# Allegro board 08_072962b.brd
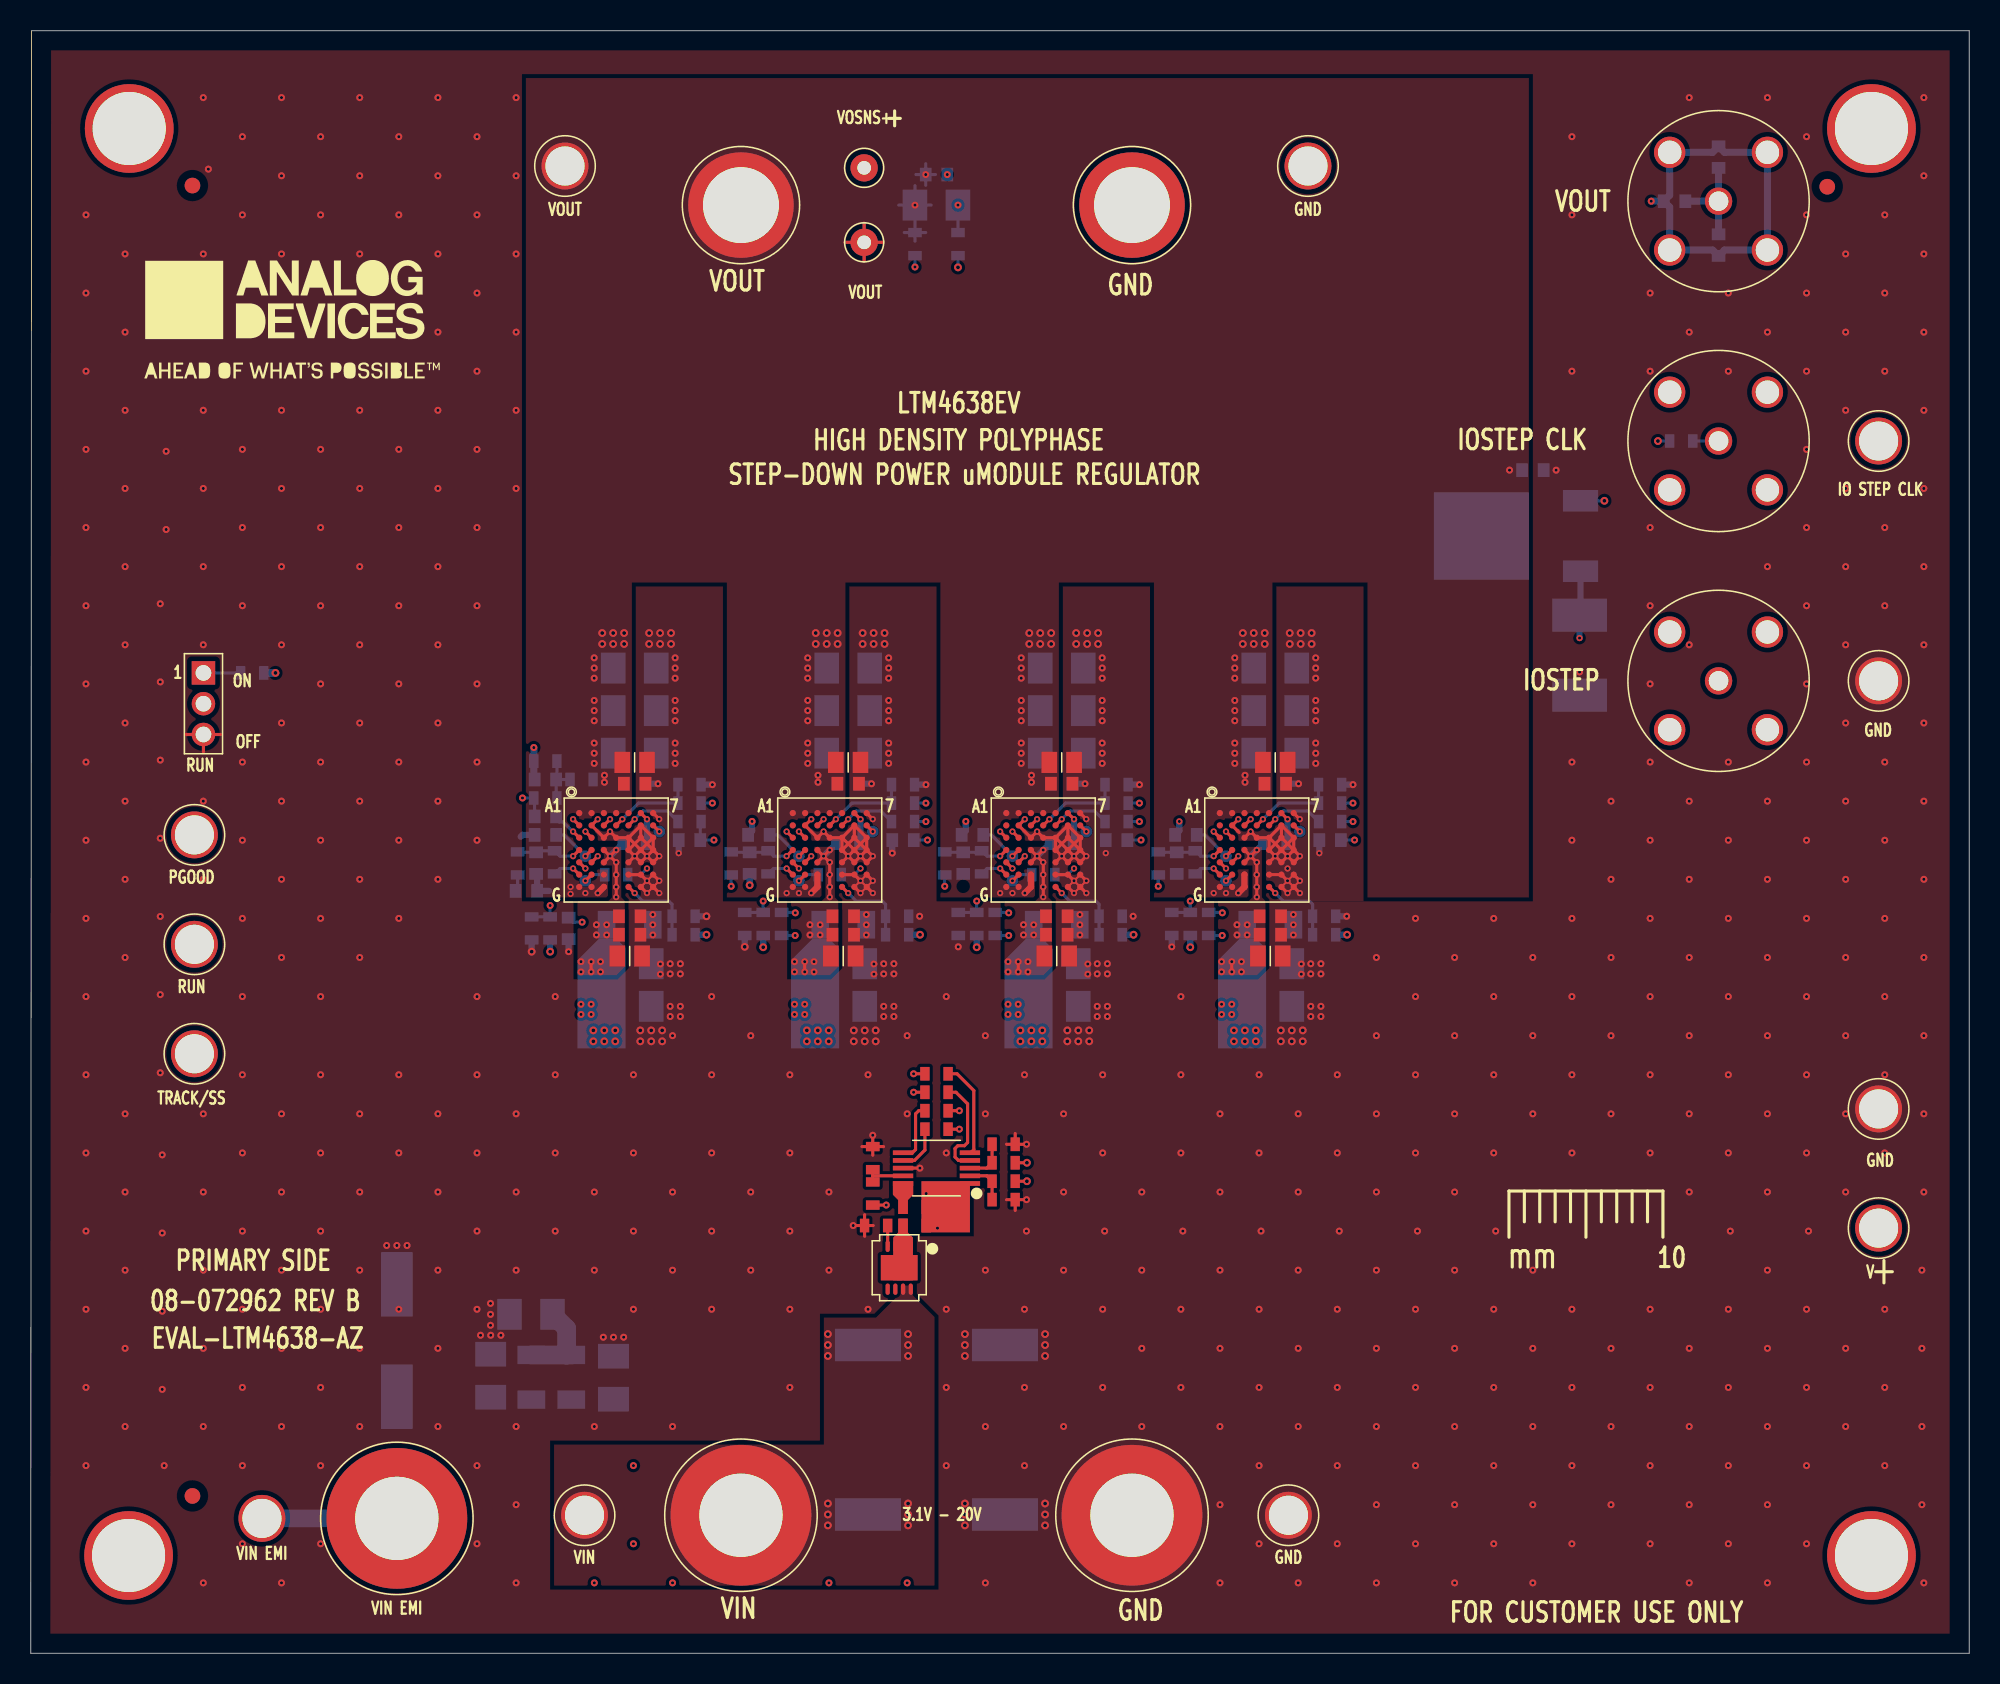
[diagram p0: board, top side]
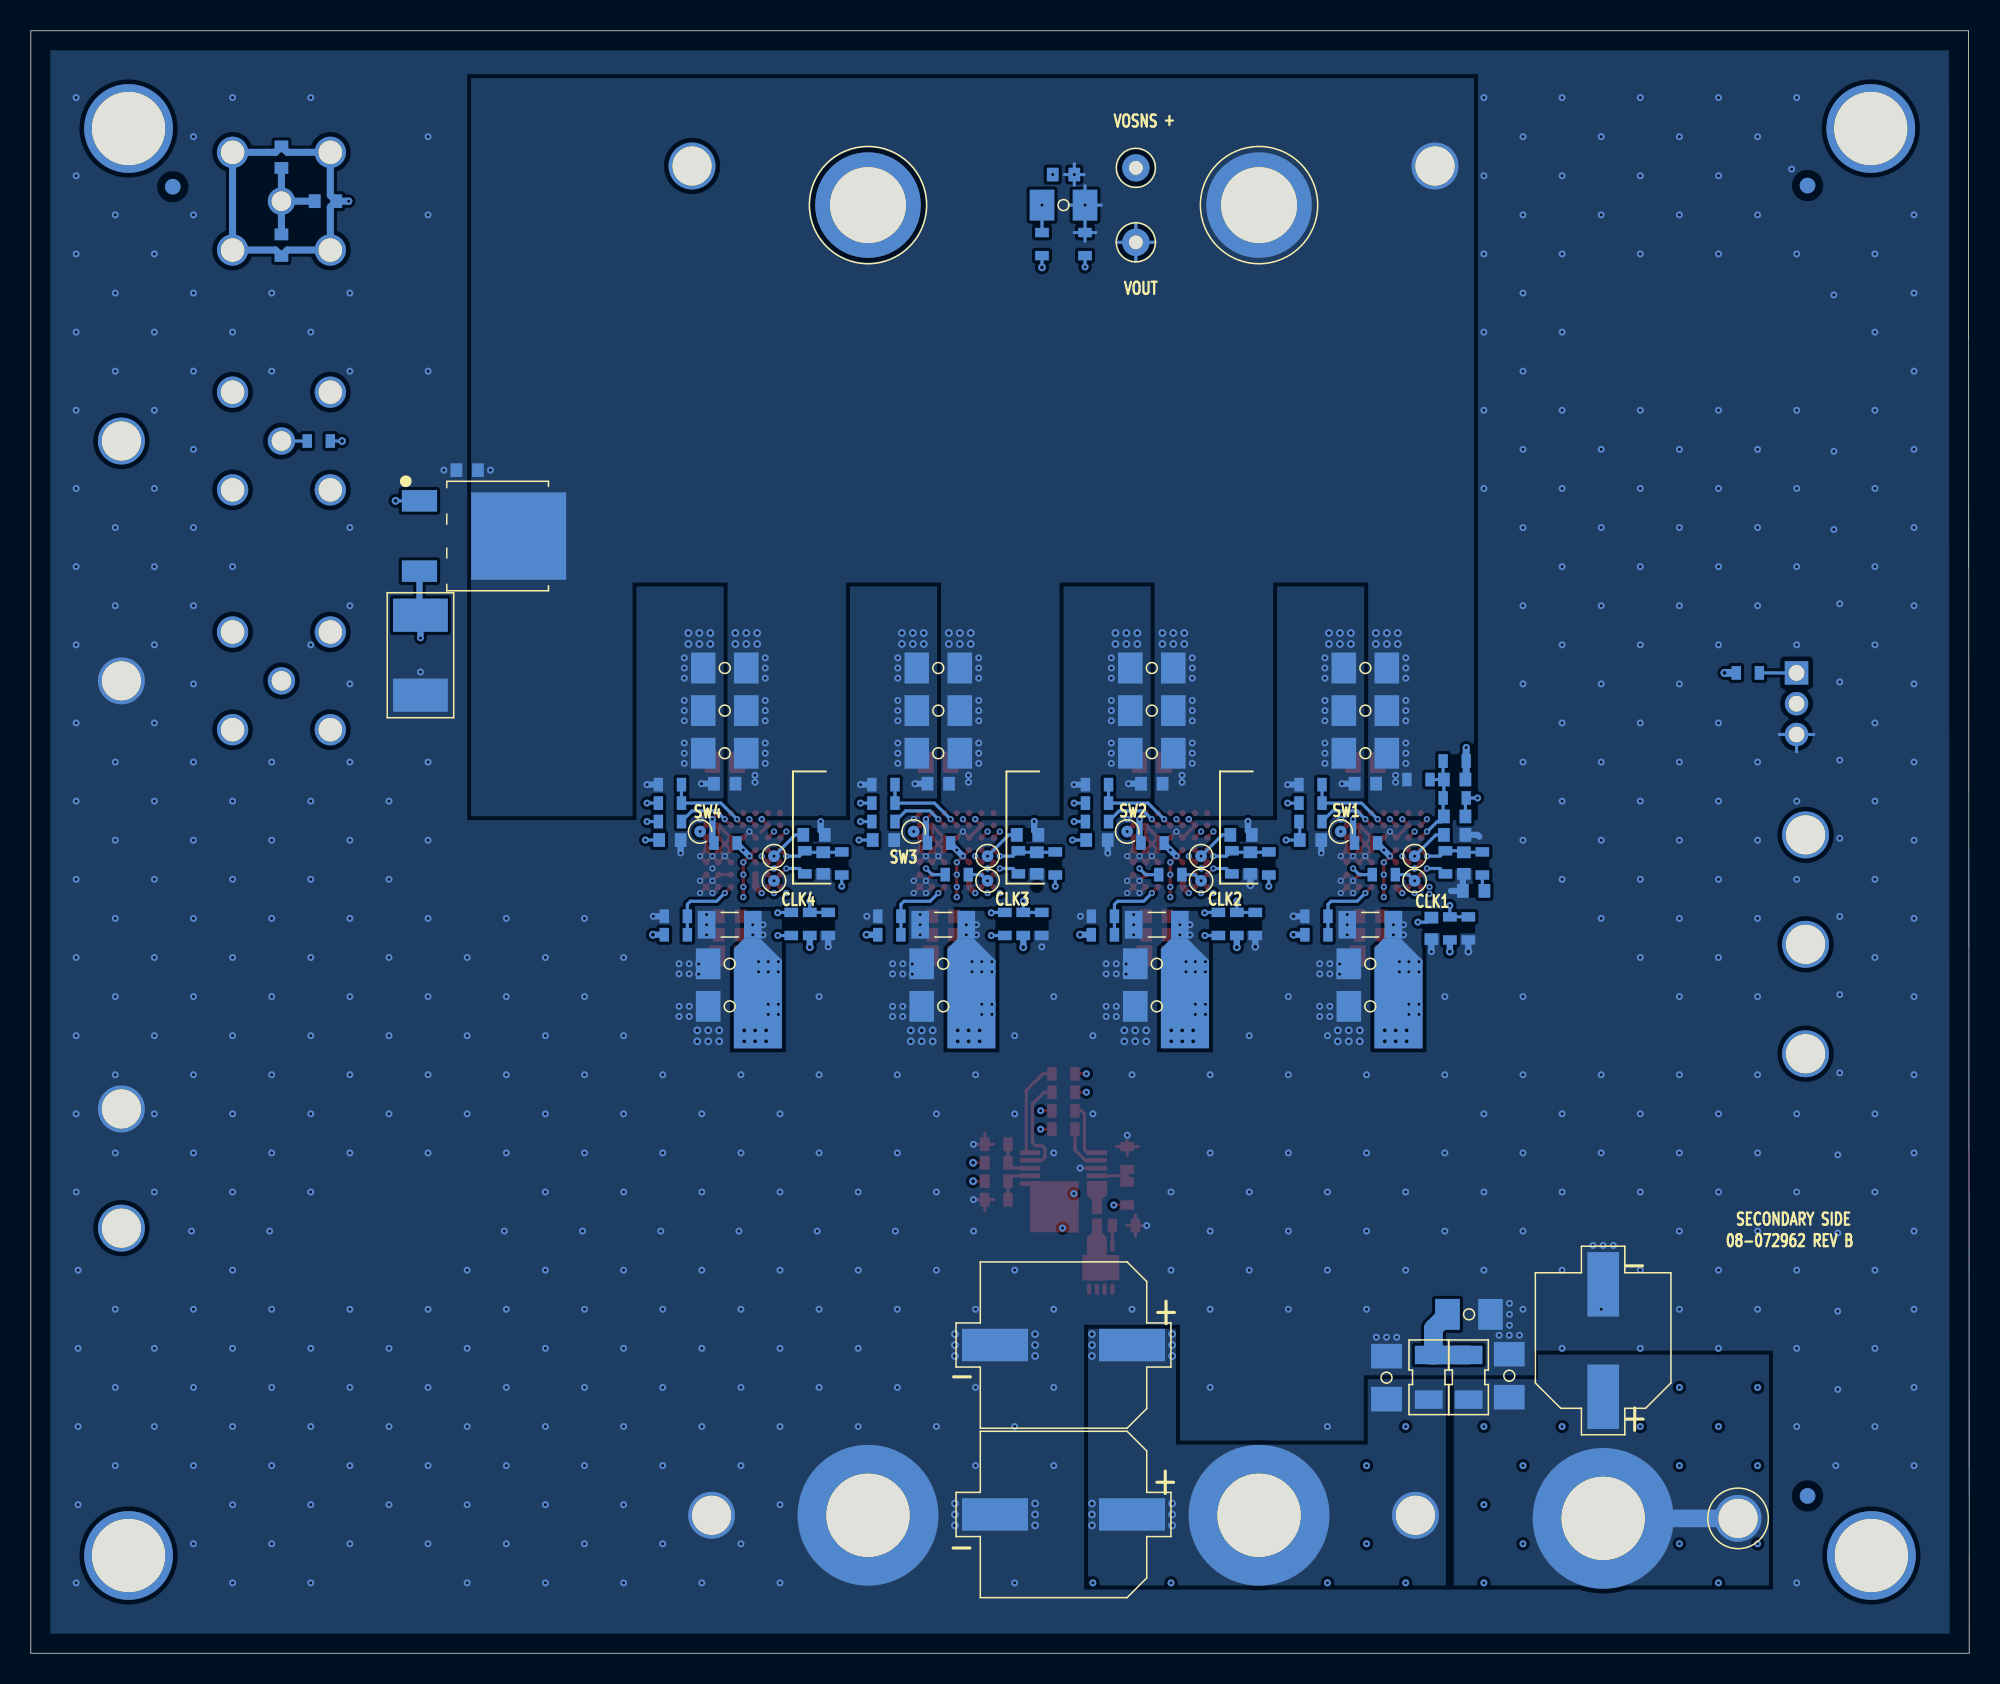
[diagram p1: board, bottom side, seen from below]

Outline 125.91 x 105.44 mm; copper layers: TOP, L2_GND, L3_SIG, L4_SIG, L5_PWR, BOTTOM. Coordinates in mm from the lower left corner of the outline.
Outline path: 0,0 125.91,0 125.91,105.44 0.05,105.44 0,0

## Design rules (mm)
constraint set DEFAULT: min track width 0.203

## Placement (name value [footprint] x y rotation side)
C2  6800pF  [C0603]  32.19 49.54 180 bottom
C4  15pF  [C0603]  32.82 51.35 90 bottom
C5  15pF  [C0603]  46.69 51.35 90 bottom
C6  0.22MF  [CPLSMSQ406H413]  58.83 9.02 0 bottom
C7  0.22MF  [CPLSMSQ406H413]  58.83 20.03 0 bottom
C8  1uF  [C0603]  38.9 47.89 0 top
C9  1uF  [C0603]  52.77 47.89 0 top
C10  22uF  [C1206H71]  38.9 44.81 0 bottom
C11  22uF  [C1206H71]  38.9 42.04 0 bottom
C12  22uF  [C1206H71]  52.77 44.81 0 bottom
C13  22uF  [C1206H71]  52.77 42.04 0 bottom
C14  22uF  [C1206H71]  66.64 44.81 0 bottom
C15  22uF  [C1206H71]  66.64 42.04 0 bottom
C16  1uF  [C0603]  39.22 56.5 0 top
C17  1uF  [C0603]  53.09 56.5 0 bottom
C18  22uF  [C1206H71]  80.51 44.81 0 bottom
C19  0.1uF  [C0603]  34.93 47.1 270 bottom
C20  22uF  [C1206H71]  80.51 42.04 0 bottom
C21  2.2UF  [C0603]  56.66 52.85 180 bottom
C22  100pF  [C0603]  33.42 56.78 0 bottom
C23  100pF  [C0603]  33.42 54.38 180 bottom
C24  2.2UF  [C0603]  42.79 52.85 180 bottom
C25  15pF  [C0603]  60.56 51.35 90 bottom
C26  15pF  [C0603]  74.43 51.35 90 bottom
C27  220uF  [C1206H71]  39.22 58.49 0 bottom
C28  220uF  [C1206H71]  39.22 61.26 0 bottom
C29  1uF  [C0603]  66.64 47.89 0 top
C30  1uF  [C0603]  80.51 47.89 0 top
C31  220uF  [C1206H71]  39.22 64.02 0 bottom
C32  220uF  [C1206H71]  53.09 64.02 0 bottom
C33  220uF  [C1206H71]  53.09 61.26 0 bottom
C34  220uF  [C1206H71]  53.09 58.49 0 bottom
C35  220uF  [C1206H71]  66.96 64.02 0 bottom
C36  220uF  [C1206H71]  66.96 61.26 0 bottom
C37  1uF  [C0603]  66.96 56.5 0 bottom
C38  1uF  [C0603]  80.83 56.5 0 top
C39  220uF  [C1206H71]  66.96 58.49 0 bottom
C40  220uF  [C1206H71]  80.83 61.26 0 bottom
C41  2.2UF  [C0603]  70.53 52.85 180 bottom
C42  2.2UF  [C0603]  84.4 52.85 180 bottom
C43  220uF  [C1206H71]  80.83 64.02 0 bottom
C44  220uF  [C1206H71]  80.83 58.49 0 bottom
C45  220uF  [CPLSMSQ327H413]  23.78 20.32 90 bottom
C46  22uF  [C1206H71]  29.87 18.03 90 bottom
C47  22uF  [C1206H71]  32.49 22.02 180 bottom
C48  22uF  [C1206H71]  37.85 17.91 90 bottom
C49  1uF  [C0603]  97.57 76.88 0 bottom
C50  1uF  [C0603]  39.22 56.5 0 bottom
C51  1uF  [C0603]  53.09 56.5 0 top
C52  1uF  [C0603]  66.96 56.5 0 top
C53  1uF  [C0603]  80.83 56.5 0 bottom
C54  68pF  [C0603]  47.29 53.18 180 bottom
C55  68pF  [C0603]  61.16 53.18 180 bottom
C56  68pF  [C0603]  75.03 53.18 180 bottom
C57  1uF  [C0603]  106.77 94.36 180 bottom
C58  1uF  [C0603]  58.83 96.09 0 bottom
C59  22uF  [C1206]  38.9 47.34 0 bottom
C60  22uF  [C1206]  52.77 47.34 0 bottom
C61  1.2uF  [C0805]  38.9 45.31 0 top
C62  1.2uF  [C0805]  52.77 45.31 0 top
C63  0.1UF  [C0603]  38.9 46.69 0 top
C64  0.1UF  [C0603]  52.77 46.69 0 top
C65  1.2uF  [C0805]  39.22 57.89 0 top
C66  1.2uF  [C0805]  53.09 57.89 0 top
C67  68pF  [C0603]  33.42 53.18 180 bottom
C68  22uF  [C1206]  66.64 47.34 0 bottom
C69  22uF  [C1206]  80.51 47.34 0 bottom
C70  1.2uF  [C0805]  66.64 45.31 0 top
C71  1.2uF  [C0805]  80.51 45.31 0 top
C72  0.1UF  [C0603]  66.64 46.69 0 top
C73  0.1UF  [C0603]  80.51 46.69 0 top
C74  1.2uF  [C0805]  66.96 57.89 0 top
C75  1.2uF  [C0805]  80.83 57.89 0 top
C76  100uF  [C1206H71]  58.83 94.11 0 bottom
C77  1uF  [C0603]  109.63 91.5 270 bottom
C78  1uF  [C0603]  109.63 97.22 90 bottom
J1  112404  [CNAMPHENOL112404]  109.63 78.78 0 top
J2  112404  [CNAMPHENOL112404]  109.63 63.19 0 top
J3  112404  [CNAMPHENOL112404]  109.63 94.36 0 top
L1  270OHM AT 100MEGHZ  [L1206H71]  32.52 17.93 90 bottom
L2  270OHM AT 100MEGHZ  [L1206H71]  35.11 17.93 270 bottom
NOREF  -  []  82.3 7.5 0 top
NOREF#2  -  []  213.61 245.52 0 top
NOREF#3  -  [unnamed#2]  6.35 6.35 0 top
NOREF#4  -  [unnamed#2]  6.39 99.09 0 top
NOREF#5  -  []  283.75 147.19 180 top
NOREF#6  -  []  224.06 43.18 0 top
NOREF#7  -  []  309.2 239.81 0 top
NOREF#8  -  []  213.57 218.87 0 top
NOREF#9  -  []  -24.03 0.3 0 top
NOREF#10  -  []  -86.46 -109.09 0 top
NOREF#11  -  []  125.91 105.44 180 top
NOREF#12  -  [unnamed#2]  10.5 95.38 0 top
NOREF#13  -  []  5.14 100.92 0 top
NOREF#14  -  []  0 0 0 top
NOREF#15  -  []  -86.46 -109.09 0 top
NOREF#16  -  []  -86.46 -109.09 0 top
NOREF#17  -  []  248.22 38.1 0 top
NOREF#18  -  []  339.91 234.72 0 top
NOREF#19  -  []  17 86.66 0 top
NOREF#20  -  []  96.02 30.04 0 top
NOREF#21  -  []  125.91 0 90 top
NOREF#22  -  []  125.91 0 0 top
NOREF#23  -  []  213.46 239.82 0 top
NOREF#24  -  []  0 0 0 top
NOREF#25  -  [unnamed#2]  116.69 95.3 0 top
NOREF#26  -  []  14.74 10.33 0 top
NOREF#27  -  []  0.05 105.44 270 top
NOREF#28  -  []  248.36 48.26 0 top
NOREF#29  -  []  -48.36 265.51 0 top
NOREF#30  -  []  0 0 0 top
NOREF#31  -  []  282.76 239.8 0 top
NOREF#32  -  []  -86.46 -109.09 0 top
NOREF#33  -  []  0.05 105.44 0 top
NOREF#34  -  []  6.35 6.35 0 top
NOREF#35  -  []  64.11 115.49 0 top
NOREF#36  -  []  307.71 229.65 0 top
NOREF#37  -  []  9.22 38.33 0 top
NOREF#38  -  []  125.91 0 90 top
NOREF#39  -  [unnamed#2]  10.5 10.22 0 top
NOREF#40  -  []  6.35 6.35 0 top
NOREF#41  -  []  0.05 105.44 0 top
NOREF#42  -  []  22.68 4.96 0 top
NOREF#43  -  []  239.65 144.53 0 top
NOREF#44  -  [unnamed#2]  119.56 6.35 0 top
NOREF#45  -  [unnamed#2]  119.56 99.09 0 top
NOREF#46  -  []  278.67 52.07 0 bottom
NOREF#47  -  [unnamed#2]  10.5 95.38 180 bottom
NOREF#48  -  [unnamed#2]  10.5 10.22 180 bottom
NOREF#49  -  [unnamed#2]  116.69 95.3 180 bottom
P3  KFH-032-10ET  [CNPEMKFH-032]  71.53 94.11 0 top
P4  KFH-032-10ET  [CNPEMKFH-032]  46.13 94.11 0 top
P5  TMM-103-02-L-S  [CNTHMHDR1X3L236W78H215]  11.22 63.7 270 top
Q1  SUD50N04-8M8P-4GE3  [TO252-3]  96.47 72.6 270 bottom
R1  0  [R0603]  33.73 47.1 90 bottom
R2  0  [R0603]  32.53 47.1 270 bottom
R3  2K  [R0603]  31.62 51.33 90 bottom
R4  0  [R0603]  47.57 47.39 90 bottom
R5  0  [R0603]  46.37 47.39 270 bottom
R6  100K  [R0603]  42.4 46.69 180 bottom
R7  100K  [R0603]  56.27 46.69 180 bottom
R8  0  [R0603]  42.79 55.25 180 bottom
R9  0  [R0603]  56.66 55.25 180 bottom
R10  0  [R0603]  45.49 51.33 90 bottom
R11  100K  [R0603]  42.4 47.89 0 bottom
R12  100K  [R0603]  56.27 47.89 0 bottom
R13  560  [R0603]  58.83 37.65 180 top
R14  0  [R0603]  42.79 56.44 180 bottom
R15  0  [R0603]  56.66 56.44 180 bottom
R16  0  [R0603]  34.02 51.4 270 bottom
R17  100K  [R0603]  39.17 52.65 0 bottom
R18  0  [R0603]  47.89 51.4 270 bottom
R19  100K  [R0603]  53.04 52.65 0 bottom
R20  0  [R0603]  48.77 47.39 270 bottom
R21  90.9K  [R0603]  35.77 56.78 180 bottom
R22  90.9K  [R0603]  33.42 55.58 180 bottom
R23  100K  [R0603]  42.79 54.05 0 bottom
R24  0  [R0603]  61.44 47.39 90 bottom
R25  0  [R0603]  60.24 47.39 270 bottom
R26  0  [R0603]  75.31 47.39 90 bottom
R27  0  [R0603]  74.11 47.39 270 bottom
R28  100K  [R0603]  70.14 46.69 180 bottom
R29  100K  [R0603]  84.01 46.69 180 bottom
R30  0  [R0603]  70.53 55.25 180 bottom
R31  0  [R0603]  59.36 51.33 90 bottom
R32  0  [R0603]  84.4 55.25 180 bottom
R33  0  [R0603]  73.23 51.33 90 bottom
R34  100K  [R0603]  70.14 47.89 0 bottom
R35  560  [R0603]  58.83 34.06 0 top
R36  100K  [R0603]  84.01 47.89 0 bottom
R37  560  [R0603]  58.83 35.25 0 top
R38  0  [R0603]  70.53 56.44 180 bottom
R39  0  [R0603]  84.4 56.44 180 bottom
R40  0  [R0603]  61.76 51.4 270 bottom
R41  100K  [R0603]  66.91 52.65 0 bottom
R42  0  [R0603]  75.63 51.4 270 bottom
R43  100K  [R0603]  80.78 52.65 0 bottom
R44  0  [R0603]  62.64 47.39 270 bottom
R45  0  [R0603]  76.51 47.39 270 bottom
R46  10  [R0603]  57.43 91.57 90 bottom
R47  10  [R0603]  60.23 91.57 90 bottom
R48  150K  [R0603]  14.38 63.7 180 bottom
R49  10K  [R0603]  107.2 78.78 180 bottom
R50  0.005  [R2512H31]  100.6 64.86 270 bottom
R51  0  [R0603]  56.66 54.05 0 bottom
R52  0  [R0603]  70.53 54.05 0 bottom
R53  0  [R0603]  84.4 54.05 0 bottom
R54  560  [R0603]  58.83 36.45 180 top
R55  560  [R0603]  38.02 50.6 0 bottom
R56  560  [R0603]  51.89 50.6 0 bottom
R57  560  [R0603]  65.76 50.6 0 bottom
R58  66.5K  [R0603]  54.91 27.79 180 top
R59  83.5K  [R0603]  57.41 28.99 180 top
R60  0  [R0603]  57.41 27.79 0 top
R61  0  [R0603]  63.19 31.87 180 top
R62  0  [R0603]  63.19 33.07 0 top
R63  0  [R0603]  54.69 29.87 90 top
R64  0  [R0603]  54.69 32.17 90 top
R65  0  [R0603]  63.19 30.67 180 top
R66  0  [R0603]  63.19 29.47 0 top
R67  90.9K  [R0603]  33.42 57.98 0 bottom
TP1  2501-2-00-80-00-00-07-0  [CNMILLMAX2501]  35.97 8.97 0 top
TP2  575-4  [CNBANANAD312LD203]  46.13 8.97 0 top
TP3  575-4  [CNBANANAD312LD203]  71.53 8.97 0 top
TP4  2501-2-00-80-00-00-07-0  [CNMILLMAX2501]  81.69 8.97 0 top
TP5  TESTPAD  [TPSMC30]  49.89 51.8 180 bottom
TP6  TESTPAD  [TPSMC30]  40.82 53.4 180 bottom
TP7  TESTPAD  [TPSMC30]  54.69 53.4 180 bottom
TP8  TESTPAD  [TPSMC30]  63.76 51.8 180 bottom
TP9  TESTPAD  [TPSMC30]  77.63 51.8 180 bottom
TP10  TESTPAD  [TPSMC30]  68.56 53.4 180 bottom
TP11  TESTPAD  [TPSMC30]  82.43 53.4 180 bottom
TP12  TP_VIA_LARGE  [TPC70D35]  54.13 96.53 0 bottom
TP13  TP_VIA_LARGE  [TPC70D35]  54.13 91.69 0 bottom
TP14  2501-2-00-80-00-00-07-0  [CNMILLMAX2501]  34.7 96.65 0 top
TP15  2501-2-00-80-00-00-07-0  [CNMILLMAX2501]  82.96 96.65 0 top
TP16  2501-2-00-80-00-00-07-0  [CNMILLMAX2501]  10.63 53.18 0 top
TP17  2501-2-00-80-00-00-07-0  [CNMILLMAX2501]  10.63 46.07 0 top
TP18  2501-2-00-80-00-00-07-0  [CNMILLMAX2501]  10.63 38.96 0 top
TP19  2501-2-00-80-00-00-07-0  [CNMILLMAX2501]  15.01 8.76 90 bottom
TP20  575-4  [CNBANANAD312LD203]  23.78 8.76 0 top
TP21  2501-2-00-80-00-00-07-0  [CNMILLMAX2501]  120.03 78.78 0 top
TP22  2501-2-00-80-00-00-07-0  [CNMILLMAX2501]  120.03 63.19 0 top
TP23  TESTPAD  [TPSMC30]  36.03 51.8 180 bottom
TP24  TESTPAD  [TPSMC30]  49.89 50.2 180 bottom
TP25  TESTPAD  [TPSMC30]  36.03 50.2 180 bottom
TP26  TESTPAD  [TPSMC30]  63.76 50.2 180 bottom
TP27  TESTPAD  [TPSMC30]  77.63 50.2 180 bottom
TP28  2501-2-00-80-00-00-07-0  [CNMILLMAX2501]  120.03 35.37 0 top
TP29  2501-2-00-80-00-00-07-0  [CNMILLMAX2501]  120.03 27.62 180 top
U1  LTM4638EY#PBF  [BGA49H211]  38.02 52.2 270 top
U2  LTM4638EY#PBF  [BGA49H211]  51.89 52.2 270 top
U3  LTM4638EY#PBF  [BGA49H211]  65.76 52.2 270 top
U4  LTM4638EY#PBF  [BGA49H211]  79.63 52.2 270 top
U5  LT3088EDD#PBF  [DFN8_3X3_PAD2_38X1_65]  56.41 25.05 180 top
U6  LTC6902CMS#PBF  [RM10]  58.83 31.52 90 top

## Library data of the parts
C2 = CAP: User Part Number: UPN; Tolerance: 10; alternate symbols: (C0603L); part number: CAP_SM-6800PF,50V,10,E005338,C0603; tolerance: 10
C4 C5 C25 C26 = CAP: User Part Number: UPN; Tolerance: 5; alternate symbols: (C0603L); part number: CAP_SM-15PF,16V,5,E027267,C0603; tolerance: 5
C6 C7 = CAPP: User Part Number: UPN; Tolerance: 20; alternate symbols: (CPLSMSQ406H413); part number: CAPP_SM-0.22MF,50V,20,E043133,CPLSMSQ406H413; tolerance: 20
C8 C9 C16 C17 C29 C30 C37 C38 C49-C53 C57 C58 C77 C78 = CAP: User Part Number: UPN; Tolerance: 10; alternate symbols: (C0603L); part number: CAP_SM-1UF,25V,10,E033832,C0603; tolerance: 10
C10-C15 C18 C20 C46-C48 = CAP: Tolerance: 10; User Part Number: UPN; alternate symbols: (C1206H71); part number: CAP_SM-22UF,25V,10,E033991,C1206H71; tolerance: 10
C19 = CAP: User Part Number: UPN; Tolerance: 10; alternate symbols: (C0603L); part number: CAP_SM-0.1UF,50V,10,E030853,C0603; tolerance: 10
C21 C24 C41 C42 = CAP: User Part Number: UPN; Tolerance: 10; alternate symbols: (C0603L); part number: CAP_SM-2.2UF,16V,10,E044611,C0603; tolerance: 10
C22 C23 = CAP: User Part Number: UPN; Tolerance: 5; alternate symbols: (C0603L); part number: CAP_SM-100PF,50V,5,E043138,C0603; tolerance: 5
C27 C28 C31-C36 C39 C40 C43 C44 = CAP: Tolerance: 20; User Part Number: UPN; alternate symbols: (C1206H71); part number: CAP_SM-220UF,6.3V,20,E027141,C1206H71; tolerance: 20
C45 = CAPP: User Part Number: UPN; Tolerance: 20; alternate symbols: (CPLSMSQ327H413); part number: CAPP_SM-220UF,35V,20,E029307,CPLSMSQ327H413; tolerance: 20
C54-C56 C67 = CAP: User Part Number: UPN; Tolerance: 5; alternate symbols: (C0603L); part number: CAP_SM-68PF,50V,5,E031470,C0603; tolerance: 5
C59 C60 C68 C69 = CAP: User Part Number: UPN; Tolerance: 10; alternate symbols: (C1206); part number: CAP_SM-22UF,16V,10,E026209,C1206; tolerance: 10
C61 C62 C65 C66 C70 C71 C74 C75 = CAP: User Part Number: UPN; Tolerance: 10; alternate symbols: (C0805L); part number: CAP_SM-1.2UF,10V,10,E019877,C0805; tolerance: 10
C63 C64 C72 C73 = CAP: User Part Number: UPN; Tolerance: 5; alternate symbols: (C0603L); part number: CAP_SM-0.1UF,50V,5,E047796,C0603; tolerance: 5
C76 = CAP: Tolerance: 20; User Part Number: UPN; alternate symbols: (C1206H71); part number: CAP_SM-100UF,10V,20,E028061,C1206H71; tolerance: 20
J1-J3 = CNBNC5P: Tolerance: N/A; User Part Number: UPN; alternate symbols: (CNAMPHENOL112404); part number: CNBNC5P_TH-112404,E020078,CNAMPHENOL112404; tolerance: N/A
L1 L2 = FERRITE: User Part Number: UPN; Tolerance: 25; alternate symbols: (L1206H71); part number: FERRITE_SM-270OHM AT 100MEGHZ,25,E040847,L1206H71; tolerance: 25
P3 P4 = CN1P: User Part Number: UPN; Tolerance: N/A; alternate symbols: (CNPEMKFH-032); part number: CN1P_TH-KFH-032-10ET,E039893,CNPEMKFH-032; tolerance: N/A
P5 = CN3P: User Part Number: UPN; Tolerance: N/A; alternate symbols: (CNTHMHDR1X3L236W78H215); part number: CN3P_TH-TMM-103-02-L-S,E033760,CNTHMHDR1X3L236W78H215; tolerance: N/A
Q1 = TRANNMOSFET_V8: Tolerance: N/A; User Part Number: UPN; alternate symbols: (TO252-3); part number: TRANNMOSFET_V8_SM-SUD50N04-8M8P-4GE3,E027839,TO252-3; tolerance: N/A
R1 R2 R4 R5 R14 R15 R24-R27 R38 R39 = RES: User Part Number: UPN; Tolerance: JUMPER; alternate symbols: (R0603L); part number: RES_SM-0,E006826,1/10W,JUMPER,R0603; tolerance: JUMPER
R3 = RES: User Part Number: UPN; Tolerance: 1; alternate symbols: (R0603L); part number: RES_SM-2K,E016458,1/10W,1,R0603; tolerance: 1
R6 R7 R11 R12 R28 R29 R34 R36 = RES: User Part Number: UPN; Tolerance: 1; alternate symbols: (R0603L); part number: RES_SM-100K,E010279,1/10W,1,R0603; tolerance: 1
R8-R10 R16 R18 R20 R30-R33 R40 R42 R44 R45 R51-R53 R60-R66 = RES: User Part Number: UPN; Tolerance: JUMPER; alternate symbols: (R0603L); part number: RES_SM-0,E007502,1/10W,JUMPER,R0603; tolerance: JUMPER
R13 R35 R37 R54-R57 = RES: User Part Number: UPN; Tolerance: 1; alternate symbols: (R0603L); part number: RES_SM-560,E004245,1/16W,1,R0603; tolerance: 1
R17 R19 R23 R41 R43 = RES: User Part Number: UPN; Tolerance: 1; alternate symbols: (R0603L); part number: RES_SM-100K,E022441,1/4W,1,R0603; tolerance: 1
R21 R22 R67 = RES: User Part Number: UPN; Tolerance: 0.1; alternate symbols: (R0603L); part number: RES_SM-90.9K,E018389,1/10W,0.1,R0603; tolerance: 0.1
R46 R47 = RES: User Part Number: UPN; Tolerance: 1; alternate symbols: (R0603L); part number: RES_SM-10,E003666,1/10W,1,R0603; tolerance: 1
R48 = RES: User Part Number: UPN; Tolerance: 1; alternate symbols: (R0603L); part number: RES_SM-150K,E003672,1/10W,1,R0603; tolerance: 1
R49 = RES: User Part Number: UPN; Tolerance: 1; alternate symbols: (R0603L); part number: RES_SM-10K,E003671,1/10W,1,R0603; tolerance: 1
R50 = RES: User Part Number: UPN; Tolerance: 1; alternate symbols: (R2512H31); part number: RES_SM-0.005,E035239,1W,1,R2512H31; tolerance: 1
R58 = RES: User Part Number: UPN; Tolerance: 1; alternate symbols: (R0603L); part number: RES_SM-66.5K,E022035,1/10W,1,R0603; tolerance: 1
R59 = RES: User Part Number: UPN; Tolerance: 0.1; alternate symbols: (R0603L); part number: RES_SM-83.5K,E059239,1/10W,0.1,R0603; tolerance: 0.1
TP1 TP4 TP14-TP19 TP21 TP22 TP28 TP29 = CNTP1P: User Part Number: UPN; Tolerance: N/A; alternate symbols: (CNMILLMAX2501); part number: CNTP1P_TH-2501-2-00-80-00-00-07-0,E031108,CNMILLMAX2501; tolerance: N/A
TP2 TP3 TP20 = CNTP1P: Tolerance: N/A; User Part Number: UPN; alternate symbols: (CNBANANAD312LD203); part number: CNTP1P_TH-575-4,E012555,CNBANANAD312LD203; tolerance: N/A
TP5-TP11 TP23-TP27 = NCTESTPAD: Tolerance: N/A; User Part Number: UPN; alternate symbols: (TPSMC30); part number: NCTESTPAD_SM-TESTPAD,E012884,TPSMC30; tolerance: N/A
TP12 TP13 = NCTESTPAD: Tolerance: N/A; User Part Number: UPN; alternate symbols: (TPC70D35); part number: NCTESTPAD_TH-TP_VIA_LARGE,E012150,TPC70D35; tolerance: N/A
U1-U4 = ADLTM4638: Tolerance: N/A; User Part Number: UPN; alternate symbols: (BGA49H211); part number: ADLTM4638_SM-LTM4638EY#PBF,E038629,BGA49H211; tolerance: N/A
U5 = LINLT3088: User Part Number: UPN; Tolerance: N/A; alternate symbols: (DFN8_3X3_PAD2_38X1_65); part number: LINLT3088_SM-LT3088EDD#PBF,E033599,DFN8_3X3_PAD2_38X1_65; tolerance: N/A
U6 = ADLTC6902: Tolerance: N/A; User Part Number: UPN; alternate symbols: (RM10); part number: ADLTC6902_SM-LTC6902CMS#PBF,E035295,RM10; tolerance: N/A

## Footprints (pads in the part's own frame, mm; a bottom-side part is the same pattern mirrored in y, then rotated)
BGA49H211
  round 0.406 smd: A1(-2.4,-2.4) A2(-2.4,-1.6) A3(-2.4,-0.8) A4(-2.4,0) A5(-2.4,0.8) A6(-2.4,1.6) A7(-2.4,2.4) B1(-1.6,-2.4) B2(-1.6,-1.6) B3(-1.6,-0.8) B4(-1.6,0) B5(-1.6,0.8) B6(-1.6,1.6) B7(-1.6,2.4) C1(-0.8,-2.4) C2(-0.8,-1.6) C3(-0.8,-0.8) C4(-0.8,0) C5(-0.8,0.8) C6(-0.8,1.6) C7(-0.8,2.4) D1(0,-2.4) D2(0,-1.6) D3(0,-0.8) D4(0,0) D5(0,0.8) D6(0,1.6) D7(0,2.4) E1(0.8,-2.4) E2(0.8,-1.6) E3(0.8,-0.8) E4(0.8,0) E5(0.8,0.8) E6(0.8,1.6) E7(0.8,2.4) F1(1.6,-2.4) F2(1.6,-1.6) F3(1.6,-0.8) F4(1.6,0) F5(1.6,0.8) F6(1.6,1.6) F7(1.6,2.4) G1(2.4,-2.4) G2(2.4,-1.6) G3(2.4,-0.8) G4(2.4,0) G5(2.4,0.8) G6(2.4,1.6) G7(2.4,2.4)
C0603
  rect 0.762x0.889 smd: 1(-0.7,0) 2(0.7,0)
C0805
  rect 1.016x1.372 smd: 1(-0.803,0) 2(0.803,0)
C1206
  rect 1.143x1.803 smd: 1(-1.5,0) 2(1.5,0)
C1206H71
  rect 1.6x2.007 smd: 1(-1.397,0) 2(1.397,0)
CNAMPHENOL112404
  round 1.778 hole 1.27: 1(0,0)
  round 2.032 hole 1.524: 2(-3.175,3.175) 3(3.175,3.175) 4(3.175,-3.175) 5(-3.175,-3.175)
CNBANANAD312LD203
  round 9.144 hole 5.41: 1(0,0)
CNMILLMAX2501
  round 3.048 hole 2.54: 1(0,0)
CNPEMKFH-032
  round 6.858 hole 4.928: 1(0,0)
CNTHMHDR1X3L236W78H215
  rect 1.524x1.524 hole 1.016: 1(0,0)
  round 1.524 hole 1.016: 2(2,0) 3(4,0)
CPLSMSQ327H413
  rect 4.191x2.057 smd: N(3.65,0) P(-3.65,0)
CPLSMSQ406H413
  rect 4.293x2.108 smd: N(4.45,0) P(-4.45,0)
DFN8_3X3_PAD2_38X1_65
  oval 0.279x0.737 smd: 1(-0.75,-1.393) 2(-0.25,-1.393) 3(0.25,-1.393) 4(0.75,-1.393) 5(0.75,1.393) 6(0.25,1.393) 7(-0.25,1.393) 8(-0.75,1.393)
  rect 2.388x1.651 smd: PAD(0,0)
L1206H71
  rect 1.194x1.803 smd: 1(-1.45,0) 2(1.45,0)
R0603
  rect 0.61x0.889 smd: 1(-0.75,0) 2(0.75,0)
R2512H31
  rect 2.159x3.556 smd: 1(-2.6,0) 2(2.6,0)
RM10
  rect 0.305x1.321 smd: 1(-1,-2.171) 2(-0.5,-2.171) 3(0,-2.171) 4(0.5,-2.171) 5(1,-2.171) 6(1,2.171) 7(0.5,2.171) 8(0,2.171) 9(-0.5,2.171) 10(-1,2.171)
TO252-3
  rect 1.397x2.286 smd: 1(-2.29,-4.191) 2(2.28,-4.191)
  rect 5.69x6.172 smd: 3(0,2.248)
TPC70D35
  round 1.778 hole 0.889: 1(0,0)
TPSMC30
  round 0.762 smd: 1(0,0)
unnamed#2
  round 5.766 hole 4.75 unplated: (0,0)

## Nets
GND: C2.1 C4.1 C5.1 C6.N(N2) C7.N(N2) C8.2(N2) C9.2(N2) C10.2(N2) C11.2(N2) C12.2(N2) C13.2(N2) C14.2(N2) C15.2(N2) C16.2(N2) C17.2(N2) C18.2(N2) C19.2(N2) C20.2(N2) C21.2(N2) C24.2(N2) C25.1 C26.1 C27.2(N2) C28.2(N2) C29.2(N2) C30.2(N2) C31.2(N2) C32.2(N2) C33.2(N2) C34.2(N2) C35.2(N2) C36.2(N2) C37.2(N2) C38.2(N2) C39.2(N2) C40.2(N2) C41.2(N2) C42.2(N2) C43.2(N2) C44.2(N2) C45.N(N2) C46.2(N2) C47.2(N2) C48.2(N2) C49.2(N2) C50.2(N2) C51.2(N2) C52.2(N2) C53.2(N2) C54.2(N2) C55.2(N2) C56.2(N2) C57.2(N2) C58.2(N2) C59.2(N2) C60.2(N2) C61.2(N2) C62.2(N2) C63.2(N2) C64.2(N2) C65.2(N2) C66.2(N2) C67.2(N2) C68.2(N2) C69.2(N2) C70.2(N2) C71.2(N2) C72.2(N2) C73.2(N2) C74.2(N2) C75.2(N2) C76.2(N2) C77.2(N2) C78.2(N2) J1.2 J1.3 J1.4 J1.5(SH4) J2.2 J2.3 J2.4 J2.5(SH4) J3.2 J3.3 J3.4 J3.5(SH4) P3.1(N1) P5.3(N3) R2.2(N2) R5.2(N2) R11.2(N2) R12.2(N2) R14.1 R15.1 R25.2(N2) R27.2(N2) R34.2(N2) R36.2(N2) R38.1 R39.1 R47.2(N2) R49.2(N2) R50.2(N2) R58.2(N2) R62.2(N2) R64.2(N2) R66.2(N2) TP3.1(N1) TP4.1(N1) TP15.1(N1) TP22.1(N1) TP28.1(N1) U1.A7 U1.B2 U1.B6 U1.C3 U1.C4 U1.C5 U1.C6 U1.C7 U1.D5 U1.D6 U1.D7 U1.E5 U1.E6 U1.E7 U1.F5 U1.F6 U1.F7 U1.G6 U1.G7 U2.A7 U2.B2 U2.B6 U2.C3 U2.C4 U2.C5 U2.C6 U2.C7 U2.D5 U2.D6 U2.D7 U2.E5 U2.E6 U2.E7 U2.F5 U2.F6 U2.F7 U2.G6 U2.G7 U3.A7 U3.B2 U3.B6 U3.C3 U3.C4 U3.C5 U3.C6 U3.C7 U3.D5 U3.D6 U3.D7 U3.E5 U3.E6 U3.E7 U3.F5 U3.F6 U3.F7 U3.G6 U3.G7 U4.A7 U4.B2 U4.B6 U4.C3 U4.C4 U4.C5 U4.C6 U4.C7 U4.D5 U4.D6 U4.D7 U4.E5 U4.E6 U4.E7 U4.F5 U4.F6 U4.F7 U4.G6 U4.G7 U6.8
VIN: C6.P C7.P C8.1 C9.1 C10.1 C11.1 C12.1 C13.1 C14.1 C15.1 C18.1 C20.1 C29.1 C30.1 C48.1 C59.1 C60.1 C61.1 C62.1 C63.1 C64.1 C68.1 C69.1 C70.1 C71.1 C72.1 C73.1 L2.2(N2) R17.1 R19.1 R41.1 R43.1 R48.1 TP1.1(N1) TP2.1(N1) U1.D3 U1.D4 U1.E3 U1.E4 U1.F4 U1.G4 U2.D3 U2.D4 U2.E3 U2.E4 U2.F4 U2.G4 U3.D3 U3.D4 U3.E3 U3.E4 U3.F4 U3.G4 U4.D3 U4.D4 U4.E3 U4.E4 U4.F4 U4.G4 U5.7 U5.8
VINEMI: C45.P C46.1 L1.1 TP19.1(N1) TP20.1(N1)
CLKIN1: C67.1 R54.2(N2) TP23.1(N1) U1.D2
CLKIN1FLT: R54.1 U6.4
CLKIN2: C54.1 R13.2(N2) R55.2(N2) TP5.1(N1) U2.D2
CLKIN2FLT: R13.1 U6.5
CLKIN3: C55.1 R37.2(N2) R56.2(N2) TP8.1(N1) U3.D2
CLKIN3FLT: R37.1 U6.6
CLKIN4: C56.1 R35.2(N2) R57.2(N2) TP9.1(N1) U4.D2
CLKIN4FLT: R35.1 U6.7
CLKOUT1: R55.1 TP25.1(N1) U1.F2
CLKOUT2: R56.1 TP24.1(N1) U2.F2
CLKOUT3: R57.1 TP26.1(N1) U3.F2
CLKOUT4: TP27.1(N1) U4.F2
COMP: C4.2(N2) R3.2(N2) R10.1 R16.1 R31.1 R33.1 U1.D1
DIV: R65.2(N2) R66.1 U6.2
FB: C22.2(N2) C23.1 R21.2(N2) R22.1 R67.2(N2) U1.C1 U2.C1 U3.C1 U4.C1
INTVCC1: C24.1 R1.1 R6.1 R23.2(N2) U1.B3
INTVCC2: C21.1 R4.1 R7.1 U2.B3
INTVCC3: C41.1 R24.1 R28.1 U3.B3
INTVCC4: C42.1 R26.1 R29.1 U4.B3
IOSTEP: J2.1 Q1.2(S) R50.1
IOSTEPCLK: J1.1 Q1.1 R49.1 TP21.1(N1)
MOD: R63.2(N2) R64.1 U6.9
PGOOD: R23.1 R51.2(N2) R52.2(N2) R53.2(N2) TP16.1(N1) U1.B5
PH: R61.2(N2) R62.1 U6.3
RUN: P5.2 R8.1 R9.1 R30.1 R32.1 TP17.1(N1)
SW1: TP6.1(N1) U1.B7
SW2: TP7.1(N1) U2.B7
SW3: TP10.1(N1) U3.B7
SW4: TP11.1(N1) U4.B7
TRACK/SS: C19.1 R20.2(N2) R44.2(N2) R45.2(N2) TP18.1(N1) U1.E2
UNNAMED_2_ADLTM4638_I1_COMPB: R16.2(N2) U1.F1
UNNAMED_2_ADLTM4638_I1_FREQ: R1.2(N2) R2.1 U1.E1
UNNAMED_2_ADLTM4638_I1_PHMODE: R6.2(N2) R11.1 U1.G5
UNNAMED_2_ADLTM4638_I1_RUN: R8.2(N2) R14.2(N2) U1.B4
UNNAMED_2_ADLTM4638_I1_TSENSE: R17.2(N2) U1.A6
UNNAMED_2_ADLTM4638_I41_COMPA: C5.2(N2) R10.2(N2) R18.1 U2.D1
UNNAMED_2_ADLTM4638_I41_COMPB: R18.2(N2) U2.F1
UNNAMED_2_ADLTM4638_I41_FREQ: R4.2(N2) R5.1 U2.E1
UNNAMED_2_ADLTM4638_I41_PGOOD: R51.1 U2.B5
UNNAMED_2_ADLTM4638_I41_PHMODE: R7.2(N2) R12.1 U2.G5
UNNAMED_2_ADLTM4638_I41_RUN: R9.2(N2) R15.2(N2) U2.B4
UNNAMED_2_ADLTM4638_I41_TRACK: R20.1 U2.E2
UNNAMED_2_ADLTM4638_I41_TSENSE: R19.2(N2) U2.A6
UNNAMED_2_ADLTM4638_I61_COMPA: C25.2(N2) R31.2(N2) R40.1 U3.D1
UNNAMED_2_ADLTM4638_I61_COMPB: R40.2(N2) U3.F1
UNNAMED_2_ADLTM4638_I61_FREQ: R24.2(N2) R25.1 U3.E1
UNNAMED_2_ADLTM4638_I61_PGOOD: R52.1 U3.B5
UNNAMED_2_ADLTM4638_I61_PHMODE: R28.2(N2) R34.1 U3.G5
UNNAMED_2_ADLTM4638_I61_RUN: R30.2(N2) R38.2(N2) U3.B4
UNNAMED_2_ADLTM4638_I61_TRACK: R44.1 U3.E2
UNNAMED_2_ADLTM4638_I61_TSENSE: R41.2(N2) U3.A6
UNNAMED_2_ADLTM4638_I71_COMPA: C26.2(N2) R33.2(N2) R42.1 U4.D1
UNNAMED_2_ADLTM4638_I71_COMPB: R42.2(N2) U4.F1
UNNAMED_2_ADLTM4638_I71_FREQ: R26.2(N2) R27.1 U4.E1
UNNAMED_2_ADLTM4638_I71_PGOOD: R53.1 U4.B5
UNNAMED_2_ADLTM4638_I71_PHMODE: R29.2(N2) R36.1 U4.G5
UNNAMED_2_ADLTM4638_I71_RUN: R32.2(N2) R39.2(N2) U4.B4
UNNAMED_2_ADLTM4638_I71_TRACK: R45.1 U4.E2
UNNAMED_2_ADLTM4638_I71_TSENSE: R43.2(N2) U4.A6
UNNAMED_2_CAP_I324_N2: C2.2(N2) R3.1
UNNAMED_3_ADLTC6902_I54_SET: R59.2(N2) U6.10
UNNAMED_3_CAP_I44_N1: C47.1 L1.2(N2) L2.1
UNNAMED_3_CN3P_I18_N1: P5.1 R48.2(N2)
UNNAMED_3_LINLT3088_I55_OUT1: R60.1 U5.1 U5.2 U5.3 U5.PAD
UNNAMED_3_LINLT3088_I55_SET: R58.1 U5.4(SET)
V+: R59.1 R60.2(N2) R61.1 R63.1 R65.1 TP29.1(N1) U6.1(V+)
VOSNS+: R46.1 TP12.1(N1) U1.B1
VOSNS-: C23.2(N2) R22.2(N2) R47.1 U1.C2 U2.C2 U3.C2 U4.C2
VOUT: C16.1 C17.1 C22.1 C27.1 C28.1 C31.1 C32.1 C33.1 C34.1 C35.1 C36.1 C37.1 C38.1 C39.1 C40.1 C43.1 C44.1 C49.1 C50.1 C51.1 C52.1 C53.1 C57.1 C58.1 C65.1 C66.1 C74.1 C75.1 C76.1 C77.1 C78.1 J3.1 P4.1(N1) Q1.3 R21.1 R46.2(N2) R67.1 TP13.1(N1) TP14.1(N1) U1.A1 U1.A2 U1.A3 U1.A4 U1.A5 U1.F3 U1.G1 U1.G2 U1.G3(VOUT_9) U2.A1 U2.A2 U2.A3 U2.A4 U2.A5 U2.F3 U2.G1 U2.G2 U2.G3(VOUT_9) U3.A1 U3.A2 U3.A3 U3.A4 U3.A5 U3.F3 U3.G1 U3.G2 U3.G3(VOUT_9) U4.A1 U4.A2 U4.A3 U4.A4 U4.A5 U4.F3 U4.G1 U4.G2 U4.G3(VOUT_9)

Pads without a net: U2 B1; U3 B1; U4 B1; U5 5 6

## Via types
v1: diameter 0.457, hole 0.203, TOP to BOTTOM, 739 vias
v2: diameter 0.508, hole 0.254, TOP to BOTTOM, 138 vias
v3: diameter 0.406, hole 0.203, TOP to BOTTOM, 143 vias

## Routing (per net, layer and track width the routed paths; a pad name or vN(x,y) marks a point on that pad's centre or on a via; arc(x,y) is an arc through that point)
GND: length 337.1
  TOP w0.133: U4.G6 81.23,49.8 v3(81.63,50.2) ; U3.G7 68.56,50.2 v3(68.56,50.2) ; U3.G7 v3(67.76,50.2) ; U3.G7 v3(67.76,49.4) ; v3(53.89,50.2) 53.49,49.8 U2.G6 ; v3(53.89,50.2) U2.F7 ; v3(53.89,50.2) U2.G7 ; U4.G7 82.43,50.2 v3(82.43,50.2) ; U4.G7 v3(81.63,49.4) ; U4.G7 v3(81.63,50.2) ; v3(67.76,50.2) U3.F7 ; v3(67.76,50.2) 67.36,49.8 U3.G6 ; v3(40.03,49.4) U1.G7 ; U1.G7 40.82,50.2 v3(40.82,50.2) ; U1.G7 v3(40.02,50.2) ; v3(81.63,50.2) U4.F7 ; U1.G6 39.62,49.8 v3(40.02,50.2) ; v3(53.89,49.4) U2.G7 ; U2.G7 54.69,50.2 v3(54.69,50.2) ; v3(40.02,50.2) U1.F7
  TOP w0.203: U2.G7 v3(54.69,49.4) ; 10.1,59.7 P5.3 ; P5.3 12.33,59.7 ; P5.3 11.22,58.59 ; U3.D5 U3.C5 ; U3.D5 U3.C6 ; U3.D5 v3(66.96,51.8) ; U3.C5 U3.D6 ; U3.C5 U3.B6 ; U3.C5 U3.C4 v3(65.36,53.4) U3.C3 U3.B2 v3(64.56,54.2) ; U1.F7 v3(40.82,50.2) ; U2.D7 v3(54.69,51.8) U2.E7 v3(53.89,51.8) ; U2.D7 U2.C7 ; U2.D7 U2.C6 ; U2.D7 v3(53.89,51.8) ; U6.8 v1(57.75,31.52) ; 63.38,29.47 R66.2 ; R66.2 63.94,28.78 ; R66.2 v1(64.68,29.47) ; v3(81.63,51.8) U4.E7 v3(82.43,51.8) U4.D7 ; v3(81.63,51.8) U4.D7 ; v3(81.63,51.8) U4.D6 ; v3(81.63,51.8) U4.E6 v3(80.83,51.8) ; U2.E5 52.69,51.4 v3(53.09,51.8) ; U4.C5 U4.C4 v3(79.23,53.4) U4.C3 ; U4.C5 U4.D6 ; U4.C5 U4.B6 ; U4.C5 U4.D5 ; U2.G6 v3(53.89,49.4) ; v3(66.96,51.8) U3.D6 ; v3(66.96,51.8) 66.56,51.4 U3.E5 ; v3(66.96,51.8) U3.E6 v3(67.76,51.8) ; U3.D6 U3.C7 ; U3.D6 v3(67.76,51.8) ; v3(78.43,54.2) U4.B2 78.39,53.44 78.39,53.44 78.49,53.34 ; v3(50.69,54.2) U2.B2 U2.C3 v3(51.49,53.4) U2.C4 U2.C5 ; v3(39.22,51.8) 38.82,51.4 U1.E5 ; v3(39.22,51.8) U1.D6 ; v3(39.22,51.8) U1.D5 ; v3(39.22,51.8) U1.E6 v3(40.02,51.8) ; U1.D7 v3(40.02,51.8) ; U1.D7 v3(40.82,51.8) U1.E7 v3(40.02,51.8) ; U1.D7 U1.C7 ; U1.D7 U1.C6 ; v3(40.02,51.8) U1.D6 ; U2.C7 U2.D6 ; U2.C7 U2.B6 ; R58.2 54.72,27.79 ; R58.2 v1(53.42,27.79) ; R58.2 54.16,28.49 ; R58.2 54.16,27.09 ; v3(53.89,50.2) U2.F6 U2.F5 ; U2.B6 U2.C6 ; U2.B6 U2.C5 ; U2.C6 U2.D5 ; v3(67.76,51.8) U3.E7 v3(68.56,51.8) U3.D7 ; v3(67.76,51.8) U3.D7 ; U1.B6 U1.C6 ; U1.B6 U1.C5 ; U1.B6 U1.C7 ; U1.C6 U1.D5 ; U2.F7 v3(54.69,50.2) ; R64.2 v1(54.69,33.66) ; R64.2 54.69,32.36 ; R64.2 53.99,32.92 ; R64.2 55.39,32.92 ; U3.C6 U3.D7 ; U3.C6 U3.B6 ; U3.D7 U3.C7 ; v3(53.89,51.8) U2.E6 v3(53.09,51.8) ; v3(53.89,51.8) U2.D6 ; U2.D5 U2.C5 ; U2.D5 v3(53.09,51.8) ; U2.C5 U2.D6 ; U2.A7 v3(54.69,54.2) ; U4.C6 U4.D5 ; U4.C6 U4.D7 ; U4.C6 U4.B6 ; U4.D5 v3(80.83,51.8) ; U1.D6 U1.C7 ; U1.D6 U1.C5 ; v3(53.09,51.8) U2.D6 ; U3.B6 U3.C7 ; U4.E5 80.43,51.4 v3(80.83,51.8) ; U3.F5 U3.F6 v3(67.76,50.2) ; U4.F5 U4.F6 v3(81.63,50.2) ; U4.D6 v3(80.83,51.8) ; U4.D6 U4.C7 ; R62.2 63.94,33.77 ; R62.2 v1(64.68,33.07) ; R62.2 63.38,33.07 ; U4.A7 v3(82.43,54.2) ; U4.D7 U4.C7 ; U1.C5 U1.C4 v3(37.63,53.4) U1.C3 U1.B2 v3(36.82,54.2) ; U1.C5 U1.D5 ; U3.A7 v3(68.56,54.2) ; v3(40.02,50.2) U1.F6 U1.F5 ; U3.F7 v3(68.56,50.2) ; U4.B6 U4.C7 ; U4.G7 v3(82.43,49.4) ; U1.G6 v3(40.02,49.4) ; U3.G7 v3(68.56,49.4) ; U4.F7 v3(82.43,50.2) ; U1.G7 v3(40.82,49.4) ; U1.A7 v3(40.82,54.2) ; U3.G6 v3(67.76,49.4) ; U4.G6 v3(81.63,49.4)
  L2_GND w0.203: 11.22,58.59 P5.3 ; P5.3 12.33,59.7 ; P5.3 10.1,59.7
  L3_SIG w0.152: P5.3 12.33,59.7 ; P5.3 11.22,58.59 ; P5.3 10.1,59.7
  L4_SIG w0.152: J2.2 J2.5 J2.4 J2.3 110.9,66.36 109.99,67.28 109.99,69.31 108.88,70.41 104.36,70.41 100.1,66.16 100.1,64.26 v1(100.6,63.77) ; J1.5 105.69,76.36 v2(105.69,78.78) 105.69,81.19 J1.2 J1.3 J1.4 110.77,75.6 109.99,74.81 109.99,72.66 108.85,71.53 103.64,71.53 99.08,76.08 v1(99.08,76.88) ; 10.1,59.7 P5.3 ; P5.3 11.22,58.59 ; P5.3 12.33,59.7 ; J3.5 J3.4 J3.3 J3.2 105.26,96.34 v1(105.26,94.36) 99.77,88.87 65.84,88.87 61.85,92.86 61.85,95.58 61.34,96.09 v1(59.53,96.09)
  L4_SIG w0.254: v3(64.56,54.2) 60.88,54.2 v1(60.73,54.06)
  L5_PWR w0.203: 11.22,58.59 P5.3 ; P5.3 10.1,59.7 ; P5.3 12.33,59.7
  L5_PWR w0.406: v3(40.82,54.2) 40.82,54.01 ; v3(54.69,54.2) 54.69,54.01 ; v3(68.56,54.2) 68.56,54.01
  BOTTOM w0.203: 11.22,58.59 P5.3 ; P5.3 12.33,59.7 ; P5.3 10.1,59.7 ; R49.2 v2(105.69,78.78) ; R47.2 v1(60.23,94.11)
  BOTTOM w0.406: C38.2 v1(82.35,56.5) ; C56.2 74.6,53.45 v3(74.6,54.06) ; 31.83,53.06 31.94,53.18 C67.2 ; R5.2 v2(46.37,45.91) ; C4.1 32.89,50.58 C2.1 33.66,49.54 ; C42.2 v3(83.7,51.99) ; C24.2 v3(42.09,51.99) ; v1(46.85,54.06) 46.85,53.44 C54.2 ; C16.2 v1(40.74,56.5) ; C51.2 v1(54.61,56.5) ; R11.2 v2(43.89,47.89) ; C5.1 v2(46.69,49.91) ; R38.1 v1(72.01,56.44) ; R15.1 v1(58.14,56.44) ; R14.1 v1(44.27,56.44) ; C55.2 60.73,53.45 v1(60.73,54.06) ; C52.2 v1(68.48,56.5) ; R27.2 v1(74.11,45.91) ; R39.1 v1(85.88,56.44) ; R36.2 v1(85.47,47.89) ; C21.2 v1(55.96,51.99) ; R2.2 v2(32.53,45.59) ; C19.2 v1(34.93,45.59)
  BOTTOM w0.457: C57.2 106.45,94.75 J3.2 109.25,97.54 C78.2 110.01,97.54 J3.3 J3.4 110.01,91.19 C77.2 109.25,91.19 J3.5 106.45,93.98 C57.2 ; C57.2 v1(105.26,94.36)
  vias: v1(3.58,93.47) v1(3.58,88.39) v1(3.58,83.31) v1(3.58,78.23) v1(3.58,73.15) v1(3.58,68.07) v1(3.58,62.99) v1(3.58,57.91) v1(3.58,52.83) v1(3.58,47.75) v1(3.58,42.67) v1(3.58,37.59) v1(3.58,32.51) v1(3.58,27.43) v1(3.58,22.35) v1(3.58,17.27) v1(3.58,12.19) v1(6.12,90.93) v1(6.12,85.85) v1(6.12,80.77) v1(6.12,75.69) v1(6.12,70.61) v1(6.12,65.53) v1(6.12,60.45) v1(6.12,55.37) v1(6.12,50.29) v1(6.12,45.21) v1(6.12,35.05) v1(6.12,29.97) v1(6.12,24.89) v1(6.12,19.81) v1(6.12,14.73) v1(8.41,68.2) v1(8.41,63.12) v1(8.41,58.04) v1(8.41,52.96) v1(8.41,47.88) v1(8.41,42.8) v1(8.41,37.72) v1(8.54,32.39) v1(8.54,27.31) v1(8.54,22.23) v1(8.54,17.15) v1(8.66,12.19) v1(8.79,88.27) v1(8.79,78.11) v1(8.79,73.03) v1(11.2,101.09) v1(11.2,90.93) v1(11.2,80.77) v1(11.2,75.69) v1(11.2,70.61) v1(11.2,65.53) v1(11.2,55.37) v1(11.2,50.29) v1(11.2,35.05) v1(11.2,29.97) v1(11.2,24.89) v1(11.2,19.81) v1(11.2,14.73) v1(11.2,4.57) v1(11.53,96.44) v1(13.74,98.55) v1(13.74,93.47) v1(13.74,78.23) v1(13.74,73.15) v1(13.74,68.07) v1(13.74,57.91) v1(13.74,52.83) v1(13.74,47.75) v1(13.74,42.67) v1(13.74,37.59) v1(13.74,32.51) v1(13.74,27.43) v1(13.74,22.35) v1(13.74,17.27) v1(13.74,12.19) v1(13.74,7.11) v1(16.28,101.09) v1(16.28,96.01) v1(16.28,90.93) v1(16.28,80.77) v1(16.28,75.69) v1(16.28,70.61) v1(16.28,65.53) v1(16.28,60.45) v1(16.28,55.37) v1(16.28,50.29) v1(16.28,45.21) v1(16.28,35.05) v1(16.28,29.97) v1(16.28,24.89) v1(16.28,19.81) v1(16.28,14.73) v1(16.28,4.57) v1(18.82,98.55) v1(18.82,93.47) v1(18.82,78.23) v1(18.82,73.15) v1(18.82,68.07) v1(18.82,62.99) v1(18.82,57.91) v1(18.82,52.83) v1(18.82,47.75) v1(18.82,42.67) v1(18.82,37.59) v1(18.82,32.51) v1(18.82,27.43) v1(18.82,22.35) v1(18.82,17.27) v1(18.82,12.19) v1(18.82,7.11) v1(21.36,101.09) v1(21.36,96.01) v1(21.36,90.93) v1(21.36,80.77) v1(21.36,75.69) v1(21.36,70.61) v1(21.36,65.53) v1(21.36,60.45) v1(21.36,55.37) v1(21.36,50.29) v1(21.36,45.21) v1(21.36,35.05) v1(21.36,29.97) v1(21.36,24.89) v1(21.36,19.81) v1(21.36,14.73) v1(23.12,26.5) v1(23.78,26.5) v1(23.9,98.55) v1(23.9,93.47) v1(23.9,78.23) v1(23.9,73.15) v1(23.9,68.07) v1(23.9,62.99) v1(23.9,57.91) v1(23.9,52.83) v1(23.9,47.75) v1(23.9,37.59) v1(23.9,32.51) v1(23.9,22.35) v1(24.44,26.5) v1(26.44,101.09) v1(26.44,96.01) v1(26.44,90.93) v1(26.44,85.85) v1(26.44,80.77) v1(26.44,75.69) v1(26.44,70.61) v1(26.44,65.53) v1(26.44,60.45) v1(26.44,55.37) v1(26.44,50.29) v1(26.44,35.05) v1(26.44,29.97) v1(26.44,24.89) v1(26.44,19.81) v1(26.44,14.73) v1(28.98,98.55) v1(28.98,93.47) v1(28.98,88.39) v1(28.98,83.31) v1(28.98,78.23) v1(28.98,73.15) v1(28.98,68.07) v1(28.98,62.99) v1(28.98,57.91) v1(28.98,52.83) v1(28.98,42.67) v1(28.98,37.59) v1(28.98,32.51) v1(28.98,27.43) v1(28.98,22.35) v1(28.98,12.19) v1(28.98,7.11) v1(29.21,20.66) v1(29.86,22.73) v1(29.86,22.02) v1(29.86,21.31) v1(29.87,20.66) v1(30.53,20.66) v1(31.52,101.09) v1(31.52,96.01) v1(31.52,90.93) v1(31.52,85.85) v1(31.52,80.77) v1(31.52,75.69) v1(31.52,35.05) v1(31.52,29.97) v1(31.52,24.89) v1(31.52,14.73) v1(31.52,9.65) v1(31.52,4.57) v1(34.06,42.67) v1(34.06,37.59) v1(34.06,32.51) v1(34.06,27.43) v1(36.6,29.97) v1(36.6,24.89) v1(36.6,14.73) v1(36.6,4.57) v1(37.19,20.54) v1(37.85,20.54) v1(38.51,20.54) v1(39.14,37.59) v1(39.14,32.51) v1(39.14,27.43) v1(39.14,22.35) v1(39.14,12.19) v1(39.14,7.11) v1(40.4,48) v1(40.4,47.34) v1(40.4,46.68) v1(40.9,44.79) v1(40.9,44.13) v1(41.53,44.81) v1(41.53,44.15) v1(41.53,42.04) v1(41.53,41.38) v1(41.68,40.13) v1(41.68,29.97) v1(41.68,24.89) v1(41.68,14.73) v1(41.68,4.57) v1(41.85,64.68) v1(41.85,64.02) v1(41.85,63.36) v1(41.85,61.92) v1(41.85,61.26) v1(41.85,60.6) v1(41.85,59.15) v1(41.85,58.49) v1(41.85,57.83) v1(42.19,44.81) v1(42.19,44.15) v1(42.19,42.04) v1(42.19,41.38) v1(44.22,42.67) v1(44.22,37.59) v1(44.22,32.51) v1(44.22,27.43) v1(44.22,22.35) v1(46.76,40.13) v1(46.76,29.97) v1(46.76,24.89) v1(49.3,37.59) v1(49.3,32.51) v1(49.3,27.43) v1(49.3,22.35) v1(49.3,17.27) v1(51.84,29.97) v1(51.84,24.89) v1(51.84,4.57) v1(54.27,48) v1(54.27,47.34) v1(54.27,46.68) v1(54.38,37.59) v1(54.38,22.35) v1(54.76,44.79) v1(54.76,44.13) v1(55.4,44.81) v1(55.4,44.15) v1(55.4,42.04) v1(55.4,41.38) v1(55.72,64.68) v1(55.72,64.02) v1(55.72,63.36) v1(55.72,61.92) v1(55.72,61.26) v1(55.72,60.6) v1(55.72,59.15) v1(55.72,58.49) v1(55.72,57.83) v1(56.06,44.81) v1(56.06,44.15) v1(56.06,42.04) v1(56.06,41.38) v1(56.92,40.13) v1(56.92,35.05) v1(56.92,4.57) v1(57.73,47.89) v1(59.46,42.67) v1(59.46,32.51) v1(59.46,22.35) v1(59.46,17.27) v1(59.46,12.19) v1(60.24,45.91) v1(62,40.13) v1(62,35.05) v1(62,24.89) v1(62,14.73) v1(62,4.57) v1(64.54,37.59) v1(64.54,22.35) v1(64.54,17.27) v1(64.54,12.19) v1(64.67,27.43) v1(67.08,35.05) v1(67.08,29.97) v1(67.08,24.89) v1(67.08,14.73) v1(68.14,48) v1(68.14,47.34) v1(68.14,46.68) v1(68.66,44.79) v1(68.66,44.13) v1(69.27,44.81) v1(69.27,44.15) v1(69.27,42.04) v1(69.27,41.38) v1(69.59,64.68) v1(69.59,64.02) v1(69.59,63.36) v1(69.59,61.92) v1(69.59,61.26) v1(69.59,60.6) v1(69.59,59.15) v1(69.59,58.49) v1(69.59,57.83) v1(69.62,37.59) v1(69.62,32.51) v1(69.62,22.35) v1(69.62,17.27) v1(69.75,27.43) v1(69.93,44.81) v1(69.93,44.15) v1(69.93,42.04) v1(69.93,41.38) v1(71.6,47.89) v1(72.16,29.97) v1(72.16,24.89) v1(72.16,19.81) v1(72.16,14.73) v1(74.7,42.67) v1(74.7,37.59) v1(74.7,32.51) v1(74.7,22.35) v1(74.7,17.27) v1(74.83,27.43) v1(77.24,35.05) v1(77.24,29.97) v1(77.24,24.89) v1(77.24,19.81) v1(77.24,14.73) v1(77.24,9.65) v1(77.24,4.57) v1(79.78,37.59) v1(79.78,32.51) v1(79.78,22.35) v1(79.78,17.27) v1(79.78,12.19) v1(79.78,7.11) v1(79.91,27.43) v1(82.01,48) v1(82.01,47.34) v1(82.01,46.68) v1(82.32,35.05) v1(82.32,29.97) v1(82.32,24.89) v1(82.32,19.81) v1(82.32,14.73) v1(82.32,4.57) v1(82.53,44.79) v1(82.53,44.13) v1(83.14,44.81) v1(83.14,44.15) v1(83.14,42.04) v1(83.14,41.38) v1(83.46,64.68) v1(83.46,64.02) v1(83.46,63.36) v1(83.46,61.92) v1(83.46,61.26) v1(83.46,60.6) v1(83.46,59.15) v1(83.46,58.49) v1(83.46,57.83) v1(83.8,44.81) v1(83.8,44.15) v1(83.8,42.04) v1(83.8,41.38) v1(84.86,37.59) v1(84.86,32.51) v1(84.86,22.35) v1(84.86,17.27) v1(84.86,12.19) v1(84.86,7.11) v1(84.99,27.43) v1(87.4,45.21) v1(87.4,40.13) v1(87.4,35.05) v1(87.4,29.97) v1(87.4,24.89) v1(87.4,19.81) v1(87.4,14.73) v1(87.4,9.65) v1(87.4,4.57) v1(89.94,47.75) v1(89.94,42.67) v1(89.94,37.59) v1(89.94,32.51) v1(89.94,22.35) v1(89.94,17.27) v1(89.94,12.19) v1(89.94,7.11) v1(90.07,27.43) v1(92.48,45.21) v1(92.48,40.13) v1(92.48,35.05) v1(92.48,29.97) v1(92.48,24.89) v1(92.48,19.81) v1(92.48,14.73) v1(92.48,9.65) v1(92.48,4.57) v1(95.02,47.75) v1(95.02,42.67) v1(95.02,37.59) v1(95.02,32.51) v1(95.02,22.35) v1(95.02,17.27) v1(95.02,12.19) v1(95.02,7.11) v1(95.15,27.43) v1(97.56,45.21) v1(97.56,40.13) v1(97.56,35.05) v1(97.56,24.89) v1(97.56,19.81) v1(97.56,14.73) v1(97.56,9.65) v1(97.56,4.57) v1(100.1,98.55) v1(100.1,93.47) v1(100.1,83.31) v1(100.1,57.91) v1(100.1,52.83) v1(100.1,47.75) v1(100.1,42.67) v1(100.1,37.59) v1(100.1,32.51) v1(100.1,22.35) v1(100.1,17.27) v1(100.1,12.19) v1(100.1,7.11) v1(102.64,55.37) v1(102.64,50.29) v1(102.64,45.21) v1(102.64,40.13) v1(102.64,35.05) v1(102.64,19.81) v1(102.64,14.73) v1(102.64,9.65) v1(105.18,88.39) v1(105.18,83.31) v1(105.18,73.15) v1(105.18,68.07) v1(105.18,62.99) v1(105.18,57.91) v1(105.18,52.83) v1(105.18,47.75) v1(105.18,42.67) v1(105.18,37.59) v1(105.18,32.51) v1(105.18,22.35) v1(105.18,17.27) v1(105.18,12.19) v1(105.18,7.11) v1(107.72,101.09) v1(107.72,85.85) v1(107.72,65.53) v1(107.72,55.37) v1(107.72,50.29) v1(107.72,45.21) v1(107.72,40.13) v1(107.72,35.05) v1(107.72,29.97) v1(107.72,19.81) v1(107.72,14.73) v1(107.72,9.65) v1(107.72,4.57) v1(110.26,88.39) v1(110.26,83.31) v1(110.26,57.91) v1(110.26,52.83) v1(110.26,47.75) v1(110.26,42.67) v1(110.26,37.59) v1(110.26,32.51) v1(110.26,22.35) v1(110.26,17.27) v1(110.26,12.19) v1(110.26,7.11) v1(110.39,27.43) v1(112.8,101.09) v1(112.8,85.85) v1(112.8,70.61) v1(112.8,55.37) v1(112.8,50.29) v1(112.8,45.21) v1(112.8,40.13) v1(112.8,35.05) v1(112.8,29.97) v1(112.8,24.89) v1(112.8,19.81) v1(112.8,14.73) v1(112.8,9.65) v1(112.8,4.57) v1(115.34,98.55) v1(115.34,93.47) v1(115.34,88.39) v1(115.34,83.31) v1(115.34,78.23) v1(115.34,73.15) v1(115.34,68.07) v1(115.34,62.99) v1(115.34,57.91) v1(115.34,52.83) v1(115.34,47.75) v1(115.34,42.67) v1(115.34,37.59) v1(115.34,32.51) v1(115.34,22.35) v1(115.34,17.27) v1(115.34,12.19) v1(115.34,7.11) v1(115.47,27.43) v1(117.88,90.93) v1(117.88,85.85) v1(117.88,80.77) v1(117.88,75.69) v1(117.88,70.61) v1(117.88,65.53) v1(117.88,60.45) v1(117.88,55.37) v1(117.88,50.29) v1(117.88,45.21) v1(117.88,40.13) v1(117.88,35.05) v1(117.88,29.97) v1(117.88,19.81) v1(117.88,14.73) v1(120.42,93.47) v1(120.42,88.39) v1(120.42,83.31) v1(120.42,73.15) v1(120.42,68.07) v1(120.42,57.91) v1(120.42,52.83) v1(120.42,47.75) v1(120.42,42.67) v1(120.42,37.59) v1(120.42,32.51) v1(120.42,22.35) v1(120.42,17.27) v1(120.42,12.19) v1(122.84,24.89) v1(122.84,19.81) v1(122.84,14.73) v1(122.84,9.65) v1(122.96,101.09) v1(122.96,96.01) v1(122.96,90.93) v1(122.96,85.85) v1(122.96,80.77) v1(122.96,75.69) v1(122.96,70.61) v1(122.96,65.53) v1(122.96,60.45) v1(122.96,55.37) v1(122.96,50.29) v1(122.96,45.21) v1(122.96,40.13) v1(122.96,35.05) v1(122.96,29.97) v1(122.96,4.57) v2(39.59,40.48) v2(39.59,39.76) v2(40.16,66.3) v2(40.16,65.59) v2(40.3,40.48) v2(40.3,39.76) v2(40.88,66.3) v2(40.88,65.59) v2(41.01,40.48) v2(41.01,39.76) v2(41.59,66.3) v2(41.59,65.59) v2(53.46,40.48) v2(53.46,39.76) v2(54.03,66.3) v2(54.03,65.59) v2(54.17,40.48) v2(54.17,39.76) v2(54.75,66.3) v2(54.75,65.59) v2(54.88,40.48) v2(54.88,39.76) v2(55.46,66.3) v2(55.46,65.59) v2(60.68,20.74) v2(60.68,20.03) v2(60.68,19.32) v2(60.68,9.73) v2(60.68,9.02) v2(60.68,8.31) v2(65.88,20.74) v2(65.88,20.03) v2(65.88,19.32) v2(65.88,9.73) v2(65.88,9.02) v2(65.88,8.31) v2(67.33,40.48) v2(67.33,39.76) v2(67.9,66.3) v2(67.9,65.59) v2(68.04,40.48) v2(68.04,39.76) v2(68.62,66.3) v2(68.62,65.59) v2(68.75,40.48) v2(68.75,39.76) v2(69.33,66.3) v2(69.33,65.59) v2(81.2,40.48) v2(81.2,39.76) v2(81.77,66.3) v2(81.77,65.59) v2(81.91,40.48) v2(81.91,39.76) v2(82.49,66.3) v2(82.49,65.59) v2(82.62,40.48) v2(82.62,39.76) v2(83.2,66.3) v2(83.2,65.59) v3(69.83,51.99) v3(81.63,51)
VIN: length 61.7
  TOP w0.203: U2.D3 v3(51.49,51.8) ; v3(51.49,51.8) U2.E4 U2.F4 U2.G4 v3(51.89,49.14) ; v3(51.49,51.8) U2.D4 ; v3(51.49,51.8) 51.09,51.4 U2.E3 ; v3(79.63,49.14) U4.G4 U4.F4 U4.E4 v3(79.23,51.8) ; v1(50.27,44.28) v1(50.27,44.94) ; v3(65.36,51.8) U3.D4 ; v3(65.36,51.8) 64.96,51.4 U3.E3 ; v3(65.36,51.8) U3.E4 U3.F4 U3.G4 v3(65.76,49.14) ; v3(65.36,51.8) U3.D3 ; v3(37.62,51.8) U1.D3 ; v3(37.62,51.8) v3(38.02,52.2) ; v3(37.62,51.8) v3(38.02,51.4) v3(38.02,50.6) v3(38.02,49.8) v3(38.02,49.14) ; v3(37.62,51.8) 37.22,51.4 U1.E3 ; v1(78.01,44.28) v1(78.01,44.94) ; v3(79.23,51.8) 78.83,51.4 U4.E3 ; v3(79.23,51.8) U4.D4 ; v3(79.23,51.8) U4.D3 ; v1(64.14,44.28) v1(64.14,44.94) ; v1(36.4,44.28) v1(36.4,44.94)
  L5_PWR w0.508: 35.63,39.64 30.11,39.64 17.38,52.37 17.38,62.22 v2(15.89,63.7)
  BOTTOM w0.406: v3(65.36,51.8) 66.16,52.6 R41.1 ; v3(79.23,51.8) 80.03,52.6 R43.1 ; R19.1 52.29,52.6 v3(51.49,51.8) ; v3(37.62,51.8) 38.42,52.6 R17.1
  BOTTOM w0.508: R48.1 v2(15.89,63.7)
  vias: v1(35.74,44.94) v1(35.74,44.28) v1(35.74,42.17) v1(35.74,41.51) v1(36.4,42.17) v1(36.4,41.51) v1(36.74,47.34) v1(36.74,46.68) v1(37.01,44.94) v1(37.01,44.28) v1(37.4,47.34) v1(37.4,46.68) v1(49.61,44.94) v1(49.61,44.28) v1(49.61,42.17) v1(49.61,41.51) v1(50.27,42.17) v1(50.27,41.51) v1(50.61,47.34) v1(50.61,46.68) v1(50.88,44.94) v1(50.88,44.28) v1(51.27,47.34) v1(51.27,46.68) v1(63.48,44.94) v1(63.48,44.28) v1(63.48,42.17) v1(63.48,41.51) v1(64.14,42.17) v1(64.14,41.51) v1(64.48,47.34) v1(64.48,46.68) v1(64.77,44.94) v1(64.77,44.28) v1(65.14,47.34) v1(65.14,46.68) v1(77.35,44.94) v1(77.35,44.28) v1(77.35,42.17) v1(77.35,41.51) v1(78.01,42.17) v1(78.01,41.51) v1(78.35,47.34) v1(78.35,46.68) v1(78.64,44.94) v1(78.64,44.28) v1(79.01,47.34) v1(79.01,46.68) v2(36.54,40.48) v2(36.54,39.76) v2(37.25,40.48) v2(37.25,39.76) v2(37.96,40.48) v2(37.96,39.76) v2(50.41,40.48) v2(50.41,39.76) v2(51.12,40.48) v2(51.12,39.76) v2(51.78,20.74) v2(51.78,20.03) v2(51.78,19.32) v2(51.78,9.73) v2(51.78,9.02) v2(51.78,8.31) v2(51.83,40.48) v2(51.83,39.76) v2(56.98,20.74) v2(56.98,20.03) v2(56.98,19.32) v2(56.98,9.73) v2(56.98,9.02) v2(56.98,8.31) v2(64.28,40.48) v2(64.28,39.76) v2(64.99,40.48) v2(64.99,39.76) v2(65.7,40.48) v2(65.7,39.76) v2(78.15,40.48) v2(78.15,39.76) v2(78.86,40.48) v2(78.86,39.76) v2(79.57,40.48) v2(79.57,39.76) v3(51.89,52.2) v3(51.89,51.4) v3(51.89,50.6) v3(51.89,49.8) v3(65.76,52.2) v3(65.76,51.4) v3(65.76,50.6) v3(65.76,49.8) v3(79.63,52.2) v3(79.63,51.4) v3(79.63,50.6) v3(79.63,49.8)
VINEMI: length 8.8
  BOTTOM w1.143: TP19.1 TP20.1
CLKIN1: length 48.3
  TOP w0.203: R54.2 v1(57.34,36.45) ; U1.D2 v3(36.03,51.8)
  L4_SIG w0.152: v1(57.34,36.45) 55.51,34.62 35.44,34.62 31.73,38.33 31.73,49.3 34.63,52.2 35.62,52.2 v3(36.03,51.8)
  BOTTOM w0.203: v3(36.03,51.8) 34.64,53.18 C67.1
CLKIN1FLT: length 6.7
  TOP w0.203: R54.1 60.09,36.45 60.85,35.7 60.85,33.18 60.65,32.98 60.21,32.98 60.04,32.8 60.04,32.25 60.26,32.02 U6.4
CLKIN2: length 48.3
  TOP w0.203: R13.2 v1(57.34,37.65) ; U2.D2 v3(49.89,51.8)
  L3_SIG w0.152: v3(49.89,51.8) 49.41,52.28 48.89,52.28 48.56,51.94 42.73,51.94 41.78,51 v3(40.02,51)
  L4_SIG w0.152: v3(49.89,51.8) 49.09,52.6 45.95,52.6 45.06,51.71 45.06,39.8 49.46,35.41 55.1,35.41 v1(57.34,37.65)
  BOTTOM w0.203: R55.2 39.62,50.6 v3(40.02,51) ; v3(49.89,51.8) 48.51,53.18 C54.1
CLKIN2FLT: length 6.3
  TOP w0.203: R13.1 60.16,37.65 61.26,36.56 61.26,32.73 61.05,32.52 U6.5
CLKIN3: length 38.7
  TOP w0.203: R37.2 v1(60.32,35.25) ; U3.D2 v3(63.76,51.8)
  L3_SIG w0.152: v3(63.76,51.8) 63.28,52.28 62.76,52.28 62.43,51.94 56.65,51.94 55.7,51 v3(53.89,51)
  L4_SIG w0.152: v3(63.76,51.8) 62.97,52.6 59.53,52.6 58.68,51.74 58.68,36.89 v1(60.32,35.25)
  BOTTOM w0.203: R56.2 53.49,50.6 v3(53.89,51) ; C55.1 62.38,53.18 v3(63.76,51.8)
CLKIN3FLT: length 3.9
  TOP w0.203: R37.1 57.67,35.25 57.47,35.05 57.47,32.73 57.27,32.52 U6.6
CLKIN4: length 50.9
  TOP w0.203: U4.D2 v3(77.63,51.8) ; R35.2 v1(60.32,34.06)
  L3_SIG w0.152: v3(67.76,51) 69.52,51 70.46,51.94 76.3,51.94 76.63,52.28 77.15,52.28 v3(77.63,51.8)
  L4_SIG w0.152: v1(60.32,34.06) 71.35,34.06 72.55,35.26 72.55,51.89 73.25,52.6 76.84,52.6 v3(77.63,51.8)
  BOTTOM w0.203: v3(67.76,51) 67.36,50.6 R57.2 ; v3(77.63,51.8) 76.25,53.18 C56.1
CLKIN4FLT: length 3.1
  TOP w0.203: U6.7 57.4,32.02 58.08,32.7 R35.1
CLKOUT1: length 2
  TOP w0.203: U1.F2 v3(36.03,50.2)
  BOTTOM w0.203: v3(36.03,50.2) U1.F2 R55.1
CLKOUT2: length 2
  TOP w0.203: U2.F2 v3(49.89,50.2)
  BOTTOM w0.203: v3(49.89,50.2) U2.F2 R56.1
CLKOUT3: length 2
  TOP w0.203: U3.F2 v3(63.76,50.2)
  BOTTOM w0.203: R57.1 U3.F2 v3(63.76,50.2)
CLKOUT4: length 0.6
  TOP w0.203: U4.F2 v3(77.63,50.2)
COMP: length 53.2
  TOP w0.203: U1.D1 v3(35.22,51.8)
  L3_SIG w0.152: v1(73.23,49.84) 72.05,48.65 63.31,48.65 62.61,47.96 60.73,47.96 59.36,49.33 v1(59.36,49.84) 56.47,49.84 55.28,48.65 49.44,48.65 48.74,47.96 46.89,47.96 45.49,49.35 v1(45.49,49.84) 42.65,49.84 41.32,48.51 35.06,48.51 34.21,49.36 34.21,51.05 34.96,51.8 v3(35.22,51.8)
  BOTTOM w0.203: R31.1 v1(59.36,49.84) ; R10.1 v1(45.49,49.84) ; R3.2 31.65,52.05 C4.2 32.92,52.15 R16.1 34.37,51.8 v3(35.22,51.8) ; R33.1 v1(73.23,49.84)
DIV: length 2.8
  TOP w0.203: U6.2 62.09,31.02 R65.2 R66.1
FB: length 52.3
  TOP w0.203: U4.C1 v3(76.83,53.4) ; U1.C1 v3(35.22,53.4) ; U3.C1 v3(62.96,53.4) ; U2.C1 v3(49.09,53.4)
  L3_SIG w0.152: v3(35.22,53.4) 35.71,52.91 43.64,52.91 44.09,53.35 44.59,53.35 45.03,52.91 48.61,52.91 v3(49.09,53.4) 49.58,52.91 57.52,52.91 57.96,53.35 58.46,53.35 58.9,52.91 62.48,52.91 v3(62.96,53.4) 63.08,53.4 63.56,52.91 71.39,52.91 71.83,53.35 72.33,53.35 72.77,52.91 76.35,52.91 v3(76.83,53.4)
  BOTTOM w0.203: v3(35.22,53.4) 35.2,53.4 34.57,54.03 34.33,54.03 34.12,54.23 C23.1 34.17,54.43 R22.1 34.12,55.63 C22.2 ; R67.2 34.17,56.83 C22.2 ; C22.2 R21.2
INTVCC1: length 28.9
  TOP w0.203: U1.B3 v3(37.63,54.2)
  L4_SIG w0.152: v2(33.73,45.59) 34.27,45.06 35.13,45.06 35.77,45.69 42.89,45.69 v2(43.89,46.69) 44.43,47.23 44.43,52.28 44.38,52.34 v1(44.38,52.85) 38.98,52.85 v3(37.63,54.2)
  BOTTOM w0.203: v1(44.38,52.85) C24.1 43.49,54 43.53,54.05 R23.2
  BOTTOM w0.406: R6.1 v2(43.89,46.69) ; R1.1 v2(33.73,45.59)
INTVCC2: length 27.5
  TOP w0.203: U2.B3 v3(51.5,54.2)
  L4_SIG w0.152: v2(47.57,45.88) 47.95,45.5 56.57,45.5 v2(57.76,46.69) 58.25,47.18 v1(58.25,52.85) 52.85,52.85 v3(51.5,54.2)
  BOTTOM w0.203: C21.1 v1(58.25,52.85)
  BOTTOM w0.406: R7.1 v2(57.76,46.69) ; R4.1 v2(47.57,45.88)
INTVCC3: length 27.5
  TOP w0.203: U3.B3 v3(65.37,54.2)
  L4_SIG w0.152: v3(65.37,54.2) 66.72,52.85 v1(72.12,52.85) 72.12,47.18 v2(71.63,46.69) 71.25,46.31 71.25,46.29 70.47,45.5 61.82,45.5 v2(61.44,45.88)
  BOTTOM w0.203: C41.1 v1(72.12,52.85)
  BOTTOM w0.406: R28.1 v2(71.63,46.69) ; R24.1 v2(61.44,45.88)
INTVCC4: length 27.3
  TOP w0.203: U4.B3 v3(79.24,54.2)
  L4_SIG w0.152: v3(79.24,54.2) 80.59,52.85 v1(85.99,52.85) 85.99,47.18 v2(85.5,46.69) 84.45,45.64 75.55,45.64 v2(75.31,45.88)
  BOTTOM w0.203: C42.1 v1(85.99,52.85)
  BOTTOM w0.406: R29.1 v2(85.5,46.69) ; R26.1 v2(75.31,45.88)
IOSTEP: length 21.4
  L4_SIG w0.152: J2.1 109.63,69.16 108.73,70.05 104.68,70.05 v3(100.6,65.97)
  BOTTOM w0.406: Q1.2 100.66,67.52 R50.1 v3(100.6,65.97)
IOSTEPCLK: length 28.6
  L3_SIG w0.152: J1.1 TP21.1
  L4_SIG w0.152: v2(102.21,74.89) 105.22,71.88 108.71,71.88 109.63,72.81 J1.1
  BOTTOM w0.203: Q1.1 v2(102.21,74.89) ; R49.1 J1.1
MOD: length 2.8
  TOP w0.203: 54.69,31.02 U6.9 ; 54.69,31.02 R63.2 ; 54.69,31.02 R64.1
PGOOD: length 86.1
  TOP w0.203: U1.B5 v3(39.22,54.2)
  L4_SIG w0.152: v1(85.88,54.05) 84.73,55.2 73.16,55.2 v1(72.01,54.05) 70.86,55.2 59.3,55.2 v1(58.14,54.05) 56.99,55.2 45.43,55.2 44.56,54.33 43.99,54.33 43.15,55.17 40.2,55.17 v3(39.22,54.2) 38.23,55.19 33.2,55.19 31.91,53.9 13.82,53.9 13.1,53.18 TP16.1
  BOTTOM w0.203: R52.2 v1(72.01,54.05) ; R53.2 v1(85.88,54.05) ; R23.1 41.34,54.74 39.76,54.74 v3(39.22,54.2) ; R51.2 v1(58.14,54.05)
PH: length 2.8
  TOP w0.203: U6.3 62.09,31.52 R61.2 R62.1
RUN: length 101.7
  L4_SIG w0.127: v1(44.27,55.25) 43.52,56 33.06,56 27.35,61.7 P5.2
  L4_SIG w0.152: v1(44.27,55.25) 45.02,56 57.39,56 v1(58.14,55.25) 58.89,56 71.26,56 v1(72.01,55.25) 72.76,56 85.13,56 v1(85.88,55.25) ; P5.2 8.98,61.7 7.78,60.5 7.78,49.83 9.35,48.26 9.35,47.34 TP17.1
  BOTTOM w0.203: R9.1 v1(58.14,55.25) ; R8.1 v1(44.27,55.25) ; R32.1 v1(85.88,55.25) ; R30.1 v1(72.01,55.25)
SW1: length 0.6
  TOP w0.203: U1.B7 v3(40.82,53.4)
SW2: length 0.6
  TOP w0.203: U2.B7 v3(54.69,53.4)
SW3: length 0.6
  TOP w0.203: U3.B7 v3(68.56,53.4)
SW4: length 0.6
  TOP w0.203: U4.B7 v3(82.43,53.4)
TRACK/SS: length 86.8
  TOP w0.203: U1.E2 v3(36.82,51.8)
  L3_SIG w0.152: v1(77.39,46.64) 77.19,46.84 74.33,46.84 73.21,45.72 64.72,45.72 63.8,46.64 v1(63.52,46.64) 63.32,46.84 60.46,46.84 59.07,45.45 51.1,45.45 49.91,46.64 v1(49.65,46.64) 49.45,46.84 46.51,46.84 45.39,45.72 36.71,45.72 35.81,46.62 v1(35.81,47.51)
  L4_SIG w0.152: TP18.1 13.33,41.66 22.71,41.66 33.61,52.56 36.06,52.56 36.82,51.8 v3(36.82,51.8) 36.82,49.97 37.23,49.57 37.23,48.93 v1(35.81,47.51)
  BOTTOM w0.203: R45.2 v1(77.39,46.64) ; C19.1 35.23,47.51 v1(35.81,47.51) ; R20.2 v1(49.65,46.64) ; R44.2 v1(63.52,46.64)
UNNAMED_2_ADLTM4638_I1_COMPB: length 1.9
  TOP w0.203: U1.F1 v3(35.22,51)
  BOTTOM w0.203: R16.2 34.37,51 v3(35.22,51)
UNNAMED_2_ADLTM4638_I1_FREQ: length 6.2
  TOP w0.203: U1.E1 v3(36.02,51)
  L4_SIG w0.152: v3(36.02,51) 35.24,50.22 34.62,50.22 34.32,49.91 34.32,49.17 v1(33.73,48.59)
  BOTTOM w0.203: v1(33.73,48.59) R1.2 R2.1
UNNAMED_2_ADLTM4638_I1_PHMODE: length 5.3
  TOP w0.203: U1.G5 v3(39.22,49.4)
  BOTTOM w0.203: v3(39.22,49.4) 39.75,48.87 41.45,48.87 41.65,48.67 R11.1 R6.2
UNNAMED_2_ADLTM4638_I1_RUN: length 5.8
  TOP w0.203: U1.B4 v3(38.42,54.2)
  BOTTOM w0.203: v3(38.42,54.2) 39.47,55.25 R8.2 R14.2
UNNAMED_2_ADLTM4638_I1_TSENSE: length 2.2
  TOP w0.203: U1.A6 v3(40.02,54.2)
  BOTTOM w0.406: R17.2 40.02,52.75 v3(40.02,54.2)
UNNAMED_2_ADLTM4638_I41_COMPA: length 4.4
  TOP w0.203: U2.D1 v3(49.09,51.8)
  BOTTOM w0.203: v3(49.09,51.8) 48.24,51.8 R18.1 47.79,52.05 C5.2 45.52,52.05 R10.2
UNNAMED_2_ADLTM4638_I41_COMPB: length 1.9
  TOP w0.203: U2.F1 v3(49.09,51)
  BOTTOM w0.203: R18.2 48.24,51 v3(49.09,51)
UNNAMED_2_ADLTM4638_I41_FREQ: length 5.9
  TOP w0.203: U2.E1 v3(49.89,51)
  L4_SIG w0.152: v1(47.57,48.88) 47.93,49.24 47.93,49.24 48.19,49.5 48.19,49.91 48.47,50.2 49.09,50.2 v3(49.89,51)
  BOTTOM w0.203: R5.1 R4.2 v1(47.57,48.88)
